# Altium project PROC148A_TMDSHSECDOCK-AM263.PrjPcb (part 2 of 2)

## Sheet PROC148A_HSECMUX.SchDoc
size 431 x 279 mm; Date: Not shown in title block; ApprovedBy: Not shown in title block; CheckedBy: Not shown in title block; Author: Not shown in title block; CompanyName: Not shown in title block; Engineer: Not shown in title block; Organization: Not shown in title block; Address1: Not shown in title block; Address2: Not shown in title block; Address3: Not shown in title block; Address4: Not shown in title block; DocumentNumber: 1; Revision: Use project parameter SCH_Rev; SheetNumber: 5; SheetTotal: 8; PageSetup: Record=PageOptions¦CenterHorizontal=True¦CenterVertical=True¦PrintScale=1.00¦XCorrection=1.00¦YCorrection=1.00¦PrintKind=0¦BorderSize=5000000¦LeftOffset=0¦BottomOffset=0¦Orientation=2¦PaperLength=1000¦PaperWidth=1000¦Scale=100¦PaperSource=15¦PrintQuality=600¦MediaType=1¦DitherType=10¦PaperKind=Letter¦PrintScaleMode=1
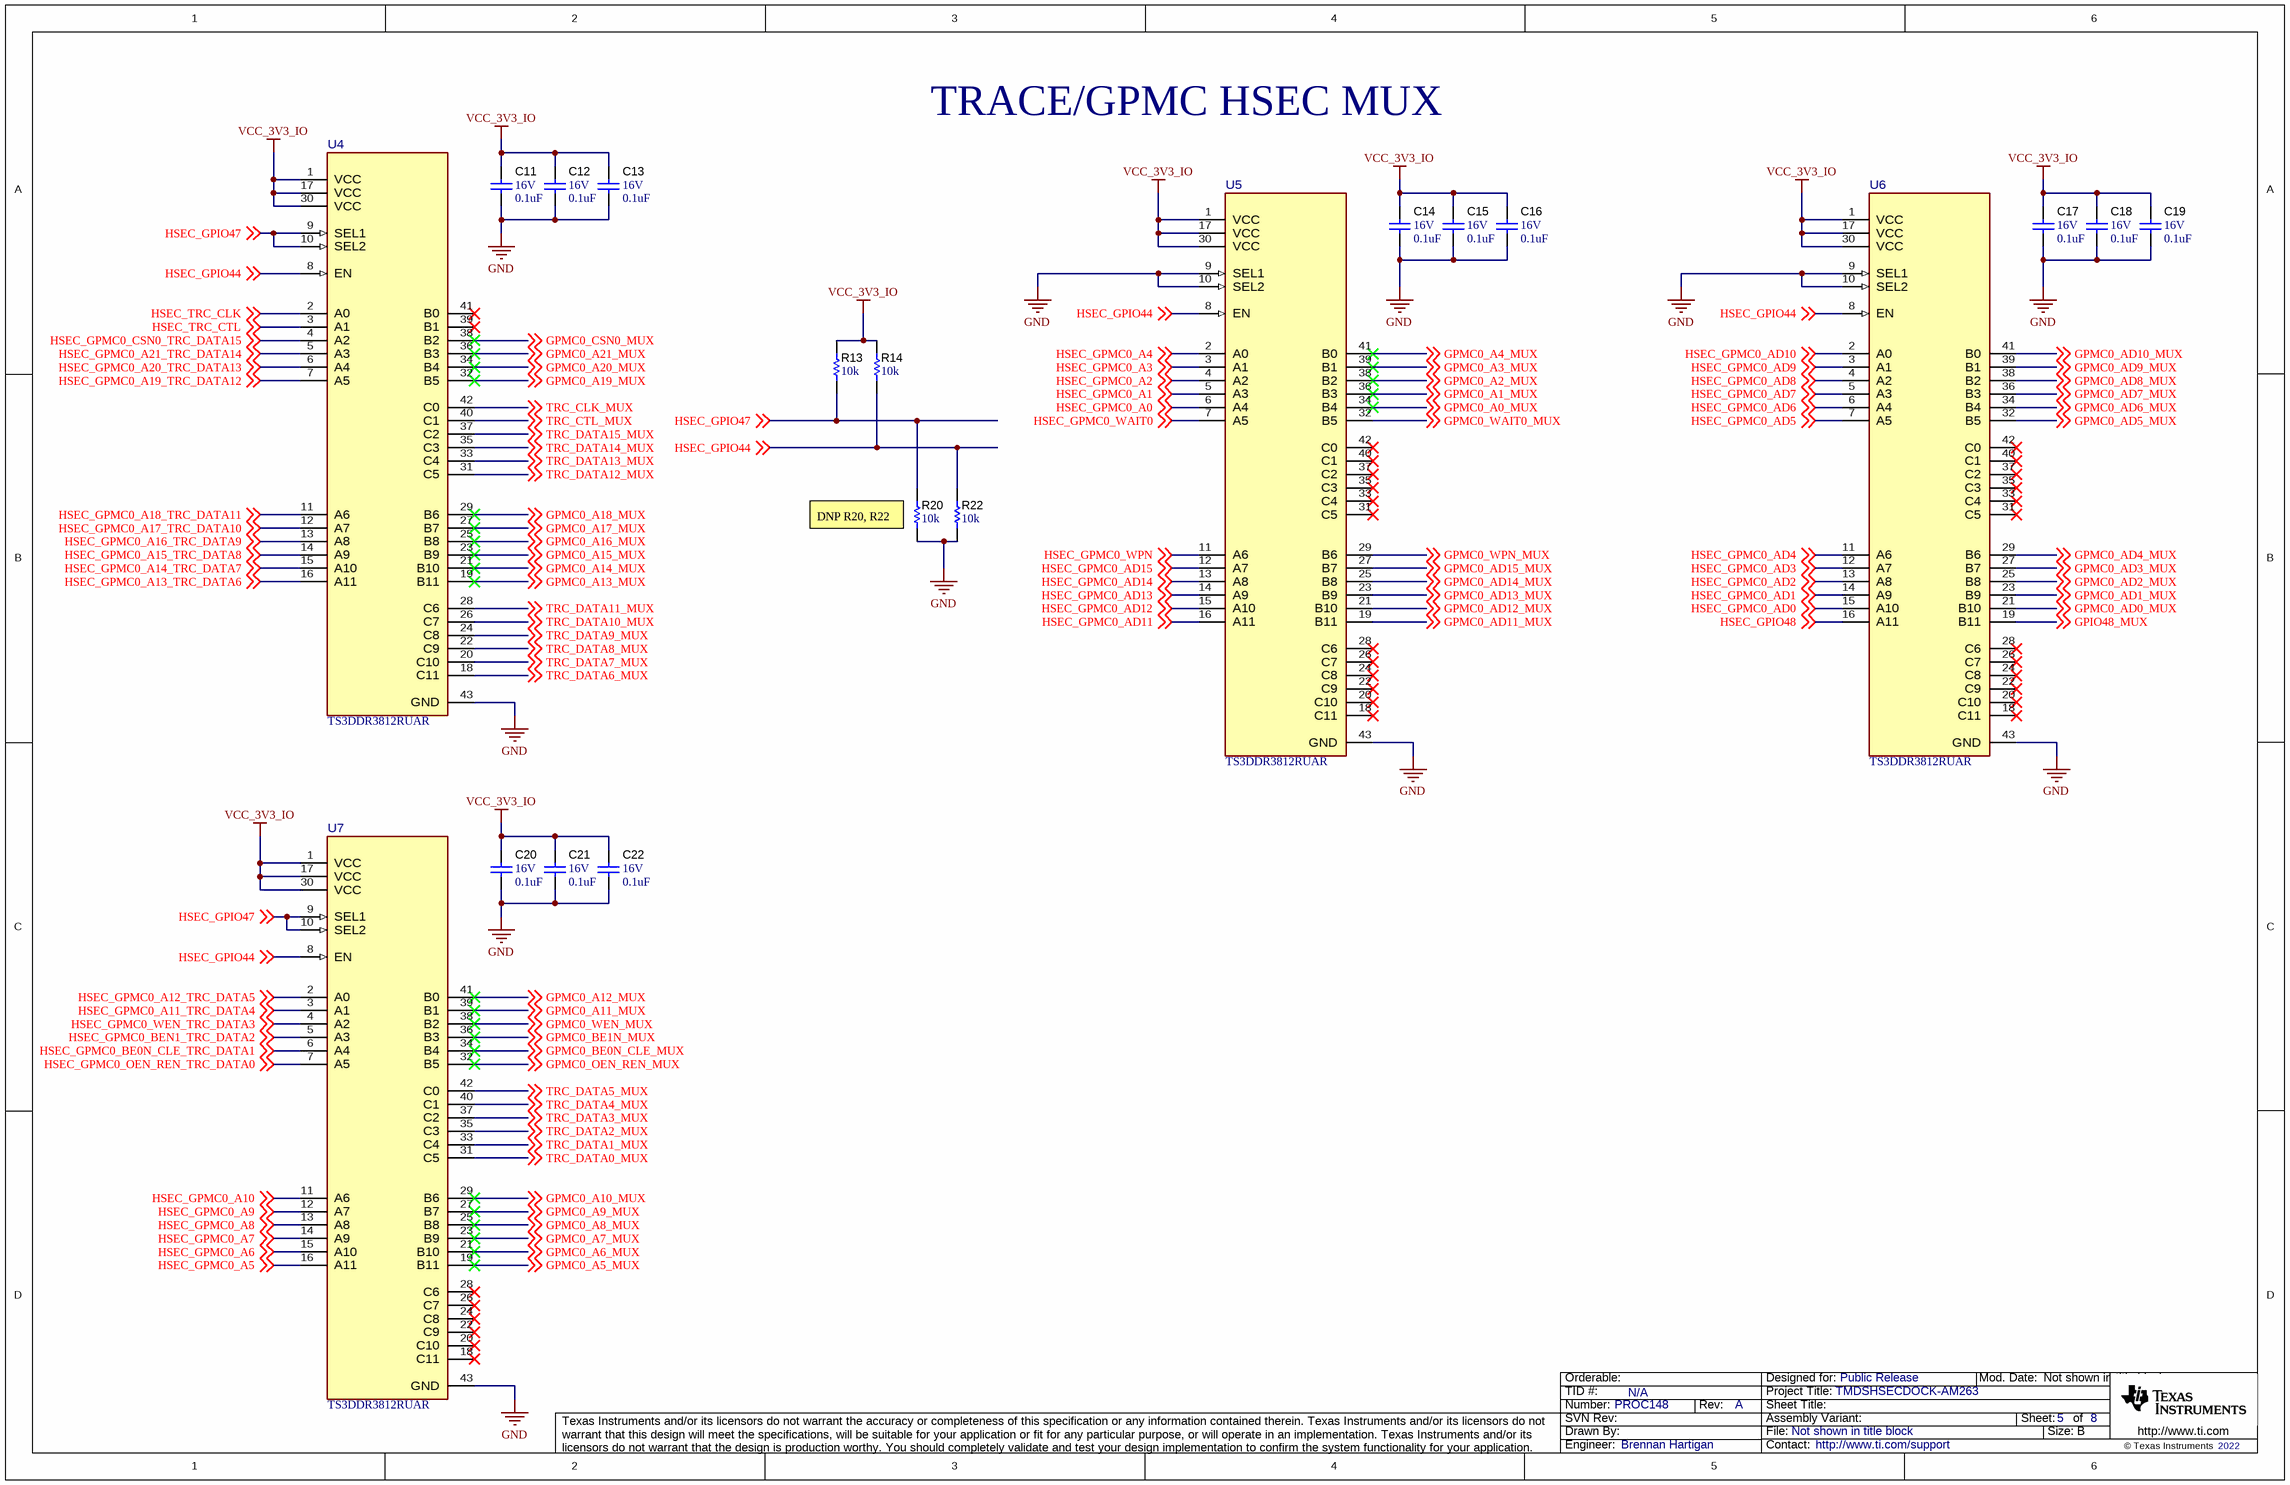
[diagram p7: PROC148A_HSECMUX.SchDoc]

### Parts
C11  VDC_V: 16V  ValueDisplayed: 0.1uF  [0201_033]  (hidden comment: GRM033R61C104KE84D)
C12  VDC_V: 16V  ValueDisplayed: 0.1uF  [0201_033]  (hidden comment: GRM033R61C104KE84D)
C13  VDC_V: 16V  ValueDisplayed: 0.1uF  [0201_033]  (hidden comment: GRM033R61C104KE84D)
C14  VDC_V: 16V  ValueDisplayed: 0.1uF  [0201_033]  (hidden comment: GRM033R61C104KE84D)
C15  VDC_V: 16V  ValueDisplayed: 0.1uF  [0201_033]  (hidden comment: GRM033R61C104KE84D)
C16  VDC_V: 16V  ValueDisplayed: 0.1uF  [0201_033]  (hidden comment: GRM033R61C104KE84D)
C17  VDC_V: 16V  ValueDisplayed: 0.1uF  [0201_033]  (hidden comment: GRM033R61C104KE84D)
C18  VDC_V: 16V  ValueDisplayed: 0.1uF  [0201_033]  (hidden comment: GRM033R61C104KE84D)
C19  VDC_V: 16V  ValueDisplayed: 0.1uF  [0201_033]  (hidden comment: GRM033R61C104KE84D)
C20  VDC_V: 16V  ValueDisplayed: 0.1uF  [0201_033]  (hidden comment: GRM033R61C104KE84D)
C21  VDC_V: 16V  ValueDisplayed: 0.1uF  [0201_033]  (hidden comment: GRM033R61C104KE84D)
C22  VDC_V: 16V  ValueDisplayed: 0.1uF  [0201_033]  (hidden comment: GRM033R61C104KE84D)
R13  ValueDisplayed: 10k  [0402]  (hidden comment: CRCW040210K0JNED)
R14  ValueDisplayed: 10k  [0402]  (hidden comment: CRCW040210K0JNED)
R20  ValueDisplayed: 10k  [0402]  (hidden comment: CRCW040210K0JNED)
R22  ValueDisplayed: 10k  [0402]  (hidden comment: CRCW040210K0JNED)
U4  TS3DDR3812RUAR  [RUA0042A-MFG]
U5  TS3DDR3812RUAR  [RUA0042A-MFG]
U6  TS3DDR3812RUAR  [RUA0042A-MFG]
U7  TS3DDR3812RUAR  [RUA0042A-MFG]

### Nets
GND: C11.2 C12.2 C13.2 C14.2 C15.2 C16.2 C17.2 C18.2 C19.2 C20.2 C21.2 C22.2 R20.1 R22.1 U4.43(GND) U5.9(SEL1) U5.10(SEL2) U5.43(GND) U6.9(SEL1) U6.10(SEL2) U6.43(GND) U7.43(GND)
VCC_3V3_IO: C11.1 C12.1 C13.1 C14.1 C15.1 C16.1 C17.1 C18.1 C19.1 C20.1 C21.1 C22.1 R13.2 R14.2 U4.1(VCC) U4.17(VCC) U4.30(VCC) U5.1(VCC) U5.17(VCC) U5.30(VCC) U6.1(VCC) U6.17(VCC) U6.30(VCC) U7.1(VCC) U7.17(VCC) U7.30(VCC)
GPIO48_MUX: U6.19(B11) ; off-sheet GPIO48_MUX
GPMC0_A0_MUX: U5.34(B4) ; off-sheet GPMC0_A0_MUX
GPMC0_A1_MUX: U5.36(B3) ; off-sheet GPMC0_A1_MUX
GPMC0_A2_MUX: U5.38(B2) ; off-sheet GPMC0_A2_MUX
GPMC0_A3_MUX: U5.39(B1) ; off-sheet GPMC0_A3_MUX
GPMC0_A4_MUX: U5.41(B0) ; off-sheet GPMC0_A4_MUX
GPMC0_A5_MUX: U7.19(B11) ; off-sheet GPMC0_A5_MUX
GPMC0_A6_MUX: U7.21(B10) ; off-sheet GPMC0_A6_MUX
GPMC0_A7_MUX: U7.23(B9) ; off-sheet GPMC0_A7_MUX
GPMC0_A8_MUX: U7.25(B8) ; off-sheet GPMC0_A8_MUX
GPMC0_A9_MUX: U7.27(B7) ; off-sheet GPMC0_A9_MUX
GPMC0_A10_MUX: U7.29(B6) ; off-sheet GPMC0_A10_MUX
GPMC0_A11_MUX: U7.39(B1) ; off-sheet GPMC0_A11_MUX
GPMC0_A12_MUX: U7.41(B0) ; off-sheet GPMC0_A12_MUX
GPMC0_A13_MUX: U4.19(B11) ; off-sheet GPMC0_A13_MUX
GPMC0_A14_MUX: U4.21(B10) ; off-sheet GPMC0_A14_MUX
GPMC0_A15_MUX: U4.23(B9) ; off-sheet GPMC0_A15_MUX
GPMC0_A16_MUX: U4.25(B8) ; off-sheet GPMC0_A16_MUX
GPMC0_A17_MUX: U4.27(B7) ; off-sheet GPMC0_A17_MUX
GPMC0_A18_MUX: U4.29(B6) ; off-sheet GPMC0_A18_MUX
GPMC0_A19_MUX: U4.32(B5) ; off-sheet GPMC0_A19_MUX
GPMC0_A20_MUX: U4.34(B4) ; off-sheet GPMC0_A20_MUX
GPMC0_A21_MUX: U4.36(B3) ; off-sheet GPMC0_A21_MUX
GPMC0_AD0_MUX: U6.21(B10) ; off-sheet GPMC0_AD0_MUX
GPMC0_AD1_MUX: U6.23(B9) ; off-sheet GPMC0_AD1_MUX
GPMC0_AD2_MUX: U6.25(B8) ; off-sheet GPMC0_AD2_MUX
GPMC0_AD3_MUX: U6.27(B7) ; off-sheet GPMC0_AD3_MUX
GPMC0_AD4_MUX: U6.29(B6) ; off-sheet GPMC0_AD4_MUX
GPMC0_AD5_MUX: U6.32(B5) ; off-sheet GPMC0_AD5_MUX
GPMC0_AD6_MUX: U6.34(B4) ; off-sheet GPMC0_AD6_MUX
GPMC0_AD7_MUX: U6.36(B3) ; off-sheet GPMC0_AD7_MUX
GPMC0_AD8_MUX: U6.38(B2) ; off-sheet GPMC0_AD8_MUX
GPMC0_AD9_MUX: U6.39(B1) ; off-sheet GPMC0_AD9_MUX
GPMC0_AD10_MUX: U6.41(B0) ; off-sheet GPMC0_AD10_MUX
GPMC0_AD11_MUX: U5.19(B11) ; off-sheet GPMC0_AD11_MUX
GPMC0_AD12_MUX: U5.21(B10) ; off-sheet GPMC0_AD12_MUX
GPMC0_AD13_MUX: U5.23(B9) ; off-sheet GPMC0_AD13_MUX
GPMC0_AD14_MUX: U5.25(B8) ; off-sheet GPMC0_AD14_MUX
GPMC0_AD15_MUX: U5.27(B7) ; off-sheet GPMC0_AD15_MUX
GPMC0_BE0N_CLE_MUX: U7.34(B4) ; off-sheet GPMC0_BE0N_CLE_MUX
GPMC0_BE1N_MUX: U7.36(B3) ; off-sheet GPMC0_BE1N_MUX
GPMC0_CSN0_MUX: U4.38(B2) ; off-sheet GPMC0_CSN0_MUX
GPMC0_OEN_REN_MUX: U7.32(B5) ; off-sheet GPMC0_OEN_REN_MUX
GPMC0_WAIT0_MUX: U5.32(B5) ; off-sheet GPMC0_WAIT0_MUX
GPMC0_WEN_MUX: U7.38(B2) ; off-sheet GPMC0_WEN_MUX
GPMC0_WPN_MUX: U5.29(B6) ; off-sheet GPMC0_WPN_MUX
HSEC_GPIO44: R14.1 R22.2 U4.8(EN) U5.8(EN) U6.8(EN) U7.8(EN) ; off-sheet HSEC_GPIO44
HSEC_GPIO47: R13.1 R20.2 U4.9(SEL1) U4.10(SEL2) U7.9(SEL1) U7.10(SEL2) ; off-sheet HSEC_GPIO47
HSEC_GPIO48: U6.16(A11) ; off-sheet HSEC_GPIO48
HSEC_GPMC0_A0: U5.6(A4) ; off-sheet HSEC_GPMC0_A0
HSEC_GPMC0_A1: U5.5(A3) ; off-sheet HSEC_GPMC0_A1
HSEC_GPMC0_A2: U5.4(A2) ; off-sheet HSEC_GPMC0_A2
HSEC_GPMC0_A3: U5.3(A1) ; off-sheet HSEC_GPMC0_A3
HSEC_GPMC0_A4: U5.2(A0) ; off-sheet HSEC_GPMC0_A4
HSEC_GPMC0_A5: U7.16(A11) ; off-sheet HSEC_GPMC0_A5
HSEC_GPMC0_A6: U7.15(A10) ; off-sheet HSEC_GPMC0_A6
HSEC_GPMC0_A7: U7.14(A9) ; off-sheet HSEC_GPMC0_A7
HSEC_GPMC0_A8: U7.13(A8) ; off-sheet HSEC_GPMC0_A8
HSEC_GPMC0_A9: U7.12(A7) ; off-sheet HSEC_GPMC0_A9
HSEC_GPMC0_A10: U7.11(A6) ; off-sheet HSEC_GPMC0_A10
HSEC_GPMC0_A11_TRC_DATA4: U7.3(A1) ; off-sheet HSEC_GPMC0_A11_TRC_DATA4
HSEC_GPMC0_A12_TRC_DATA5: U7.2(A0) ; off-sheet HSEC_GPMC0_A12_TRC_DATA5
HSEC_GPMC0_A13_TRC_DATA6: U4.16(A11) ; off-sheet HSEC_GPMC0_A13_TRC_DATA6
HSEC_GPMC0_A14_TRC_DATA7: U4.15(A10) ; off-sheet HSEC_GPMC0_A14_TRC_DATA7
HSEC_GPMC0_A15_TRC_DATA8: U4.14(A9) ; off-sheet HSEC_GPMC0_A15_TRC_DATA8
HSEC_GPMC0_A16_TRC_DATA9: U4.13(A8) ; off-sheet HSEC_GPMC0_A16_TRC_DATA9
HSEC_GPMC0_A17_TRC_DATA10: U4.12(A7) ; off-sheet HSEC_GPMC0_A17_TRC_DATA10
HSEC_GPMC0_A18_TRC_DATA11: U4.11(A6) ; off-sheet HSEC_GPMC0_A18_TRC_DATA11
HSEC_GPMC0_A19_TRC_DATA12: U4.7(A5) ; off-sheet HSEC_GPMC0_A19_TRC_DATA12
HSEC_GPMC0_A20_TRC_DATA13: U4.6(A4) ; off-sheet HSEC_GPMC0_A20_TRC_DATA13
HSEC_GPMC0_A21_TRC_DATA14: U4.5(A3) ; off-sheet HSEC_GPMC0_A21_TRC_DATA14
HSEC_GPMC0_AD0: U6.15(A10) ; off-sheet HSEC_GPMC0_AD0
HSEC_GPMC0_AD1: U6.14(A9) ; off-sheet HSEC_GPMC0_AD1
HSEC_GPMC0_AD2: U6.13(A8) ; off-sheet HSEC_GPMC0_AD2
HSEC_GPMC0_AD3: U6.12(A7) ; off-sheet HSEC_GPMC0_AD3
HSEC_GPMC0_AD4: U6.11(A6) ; off-sheet HSEC_GPMC0_AD4
HSEC_GPMC0_AD5: U6.7(A5) ; off-sheet HSEC_GPMC0_AD5
HSEC_GPMC0_AD6: U6.6(A4) ; off-sheet HSEC_GPMC0_AD6
HSEC_GPMC0_AD7: U6.5(A3) ; off-sheet HSEC_GPMC0_AD7
HSEC_GPMC0_AD8: U6.4(A2) ; off-sheet HSEC_GPMC0_AD8
HSEC_GPMC0_AD9: U6.3(A1) ; off-sheet HSEC_GPMC0_AD9
HSEC_GPMC0_AD10: U6.2(A0) ; off-sheet HSEC_GPMC0_AD10
HSEC_GPMC0_AD11: U5.16(A11) ; off-sheet HSEC_GPMC0_AD11
HSEC_GPMC0_AD12: U5.15(A10) ; off-sheet HSEC_GPMC0_AD12
HSEC_GPMC0_AD13: U5.14(A9) ; off-sheet HSEC_GPMC0_AD13
HSEC_GPMC0_AD14: U5.13(A8) ; off-sheet HSEC_GPMC0_AD14
HSEC_GPMC0_AD15: U5.12(A7) ; off-sheet HSEC_GPMC0_AD15
HSEC_GPMC0_BE0N_CLE_TRC_DATA1: U7.6(A4) ; off-sheet HSEC_GPMC0_BE0N_CLE_TRC_DATA1
HSEC_GPMC0_BEN1_TRC_DATA2: U7.5(A3) ; off-sheet HSEC_GPMC0_BEN1_TRC_DATA2
HSEC_GPMC0_CSN0_TRC_DATA15: U4.4(A2) ; off-sheet HSEC_GPMC0_CSN0_TRC_DATA15
HSEC_GPMC0_OEN_REN_TRC_DATA0: U7.7(A5) ; off-sheet HSEC_GPMC0_OEN_REN_TRC_DATA0
HSEC_GPMC0_WAIT0: U5.7(A5) ; off-sheet HSEC_GPMC0_WAIT0
HSEC_GPMC0_WEN_TRC_DATA3: U7.4(A2) ; off-sheet HSEC_GPMC0_WEN_TRC_DATA3
HSEC_GPMC0_WPN: U5.11(A6) ; off-sheet HSEC_GPMC0_WPN
HSEC_TRC_CLK: U4.2(A0) ; off-sheet HSEC_TRC_CLK
HSEC_TRC_CTL: U4.3(A1) ; off-sheet HSEC_TRC_CTL
TRC_CLK_MUX: U4.42(C0) ; off-sheet TRC_CLK_MUX
TRC_CTL_MUX: U4.40(C1) ; off-sheet TRC_CTL_MUX
TRC_DATA0_MUX: U7.31(C5) ; off-sheet TRC_DATA0_MUX
TRC_DATA1_MUX: U7.33(C4) ; off-sheet TRC_DATA1_MUX
TRC_DATA2_MUX: U7.35(C3) ; off-sheet TRC_DATA2_MUX
TRC_DATA3_MUX: U7.37(C2) ; off-sheet TRC_DATA3_MUX
TRC_DATA4_MUX: U7.40(C1) ; off-sheet TRC_DATA4_MUX
TRC_DATA5_MUX: U7.42(C0) ; off-sheet TRC_DATA5_MUX
TRC_DATA6_MUX: U4.18(C11) ; off-sheet TRC_DATA6_MUX
TRC_DATA7_MUX: U4.20(C10) ; off-sheet TRC_DATA7_MUX
TRC_DATA8_MUX: U4.22(C9) ; off-sheet TRC_DATA8_MUX
TRC_DATA9_MUX: U4.24(C8) ; off-sheet TRC_DATA9_MUX
TRC_DATA10_MUX: U4.26(C7) ; off-sheet TRC_DATA10_MUX
TRC_DATA11_MUX: U4.28(C6) ; off-sheet TRC_DATA11_MUX
TRC_DATA12_MUX: U4.31(C5) ; off-sheet TRC_DATA12_MUX
TRC_DATA13_MUX: U4.33(C4) ; off-sheet TRC_DATA13_MUX
TRC_DATA14_MUX: U4.35(C3) ; off-sheet TRC_DATA14_MUX
TRC_DATA15_MUX: U4.37(C2) ; off-sheet TRC_DATA15_MUX

Not connected (* = marked no-connect by the designer): U4 39(B1)* 41(B0)*; U5 18(C11)* 20(C10)* 22(C9)* 24(C8)* 26(C7)* 28(C6)* 31(C5)* 33(C4)* 35(C3)* 37(C2)* 40(C1)* 42(C0)*; U6 18(C11)* 20(C10)* 22(C9)* 24(C8)* 26(C7)* 28(C6)* 31(C5)* 33(C4)* 35(C3)* 37(C2)* 40(C1)* 42(C0)*; U7 18(C11)* 20(C10)* 22(C9)* 24(C8)* 26(C7)* 28(C6)*

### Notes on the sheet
- TRACE/GPMC HSEC MUX
- (near R20) DNP R20, R22

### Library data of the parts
C11-C22 = CMP-0009717-2: CAP, CERM, 0.1 uF, 16 V, +/- 10%, X5R, 0201; Manufacturer: MuRata; TaMin_C: -55°C; Polarized: N; SizeAreaWB_mm2: 2.08; Value1: Unknown; U/M: EA; Value: 0.1uF; TaMax_C: 85°C; SizeZ_mm: 0.33; SizeX_mm: 0.6; SizeY_mm: 0.3; Cap_Case: 0201; SizeArea_mm2: 0.18; Cap_F: 100nF; AEC Category: Q200
R13 R14 R20 R22 = CMP-0026825-5: RES, 10 k, 5%, 0.063 W, AEC-Q200 Grade 0, 0402; Manufacturer: Vishay-Dale; Power_W: 63mW; TempCo: 200 ppm/C; Value_Code: 10k0; Value: 10k; EIA_Code: E24; SizeX_mm: 1; SizeY_mm: 0.5; SizeZ_mm: 0.6; Value2: 0.063W; AEC Qualified: Y; VDC_V: 50V; AEC Category: Q200; AEC Grade: 0
U4-U7 = CMP-0093539-2: IC MUX/DEMUX DDR3 1:2 42WQFN; Manufacturer: Texas Instruments; TaMax_C: +85°C; AEC Qualified: No; Nominal Supply Current: 300uA; On State Resistance: 8Ω; Standoff Height: 0mm; Min Supply Voltage: 3V; Max Supply Voltage: 3.6V; AEC Category: Q200; SizeZ_mm: 0.8mm; TaMin_C: -40°C; PositionCount: 12; -3Db Bandwith: 1.675GHz

## Sheet PROC148A_PSRAM.SchDoc
size 431 x 279 mm; Date: Not shown in title block; ApprovedBy: Not shown in title block; CheckedBy: Not shown in title block; Author: Not shown in title block; CompanyName: Not shown in title block; Engineer: Not shown in title block; Organization: Not shown in title block; Address1: Not shown in title block; Address2: Not shown in title block; Address3: Not shown in title block; Address4: Not shown in title block; DocumentNumber: 1; Revision: Use project parameter SCH_Rev; SheetNumber: 6; SheetTotal: 8; PageSetup: Record=PageOptions¦CenterHorizontal=True¦CenterVertical=True¦PrintScale=1.00¦XCorrection=1.00¦YCorrection=1.00¦PrintKind=0¦BorderSize=5000000¦LeftOffset=0¦BottomOffset=0¦Orientation=2¦PaperLength=1000¦PaperWidth=1000¦Scale=100¦PaperSource=15¦PrintQuality=600¦MediaType=1¦DitherType=10¦PaperKind=Letter¦PrintScaleMode=1
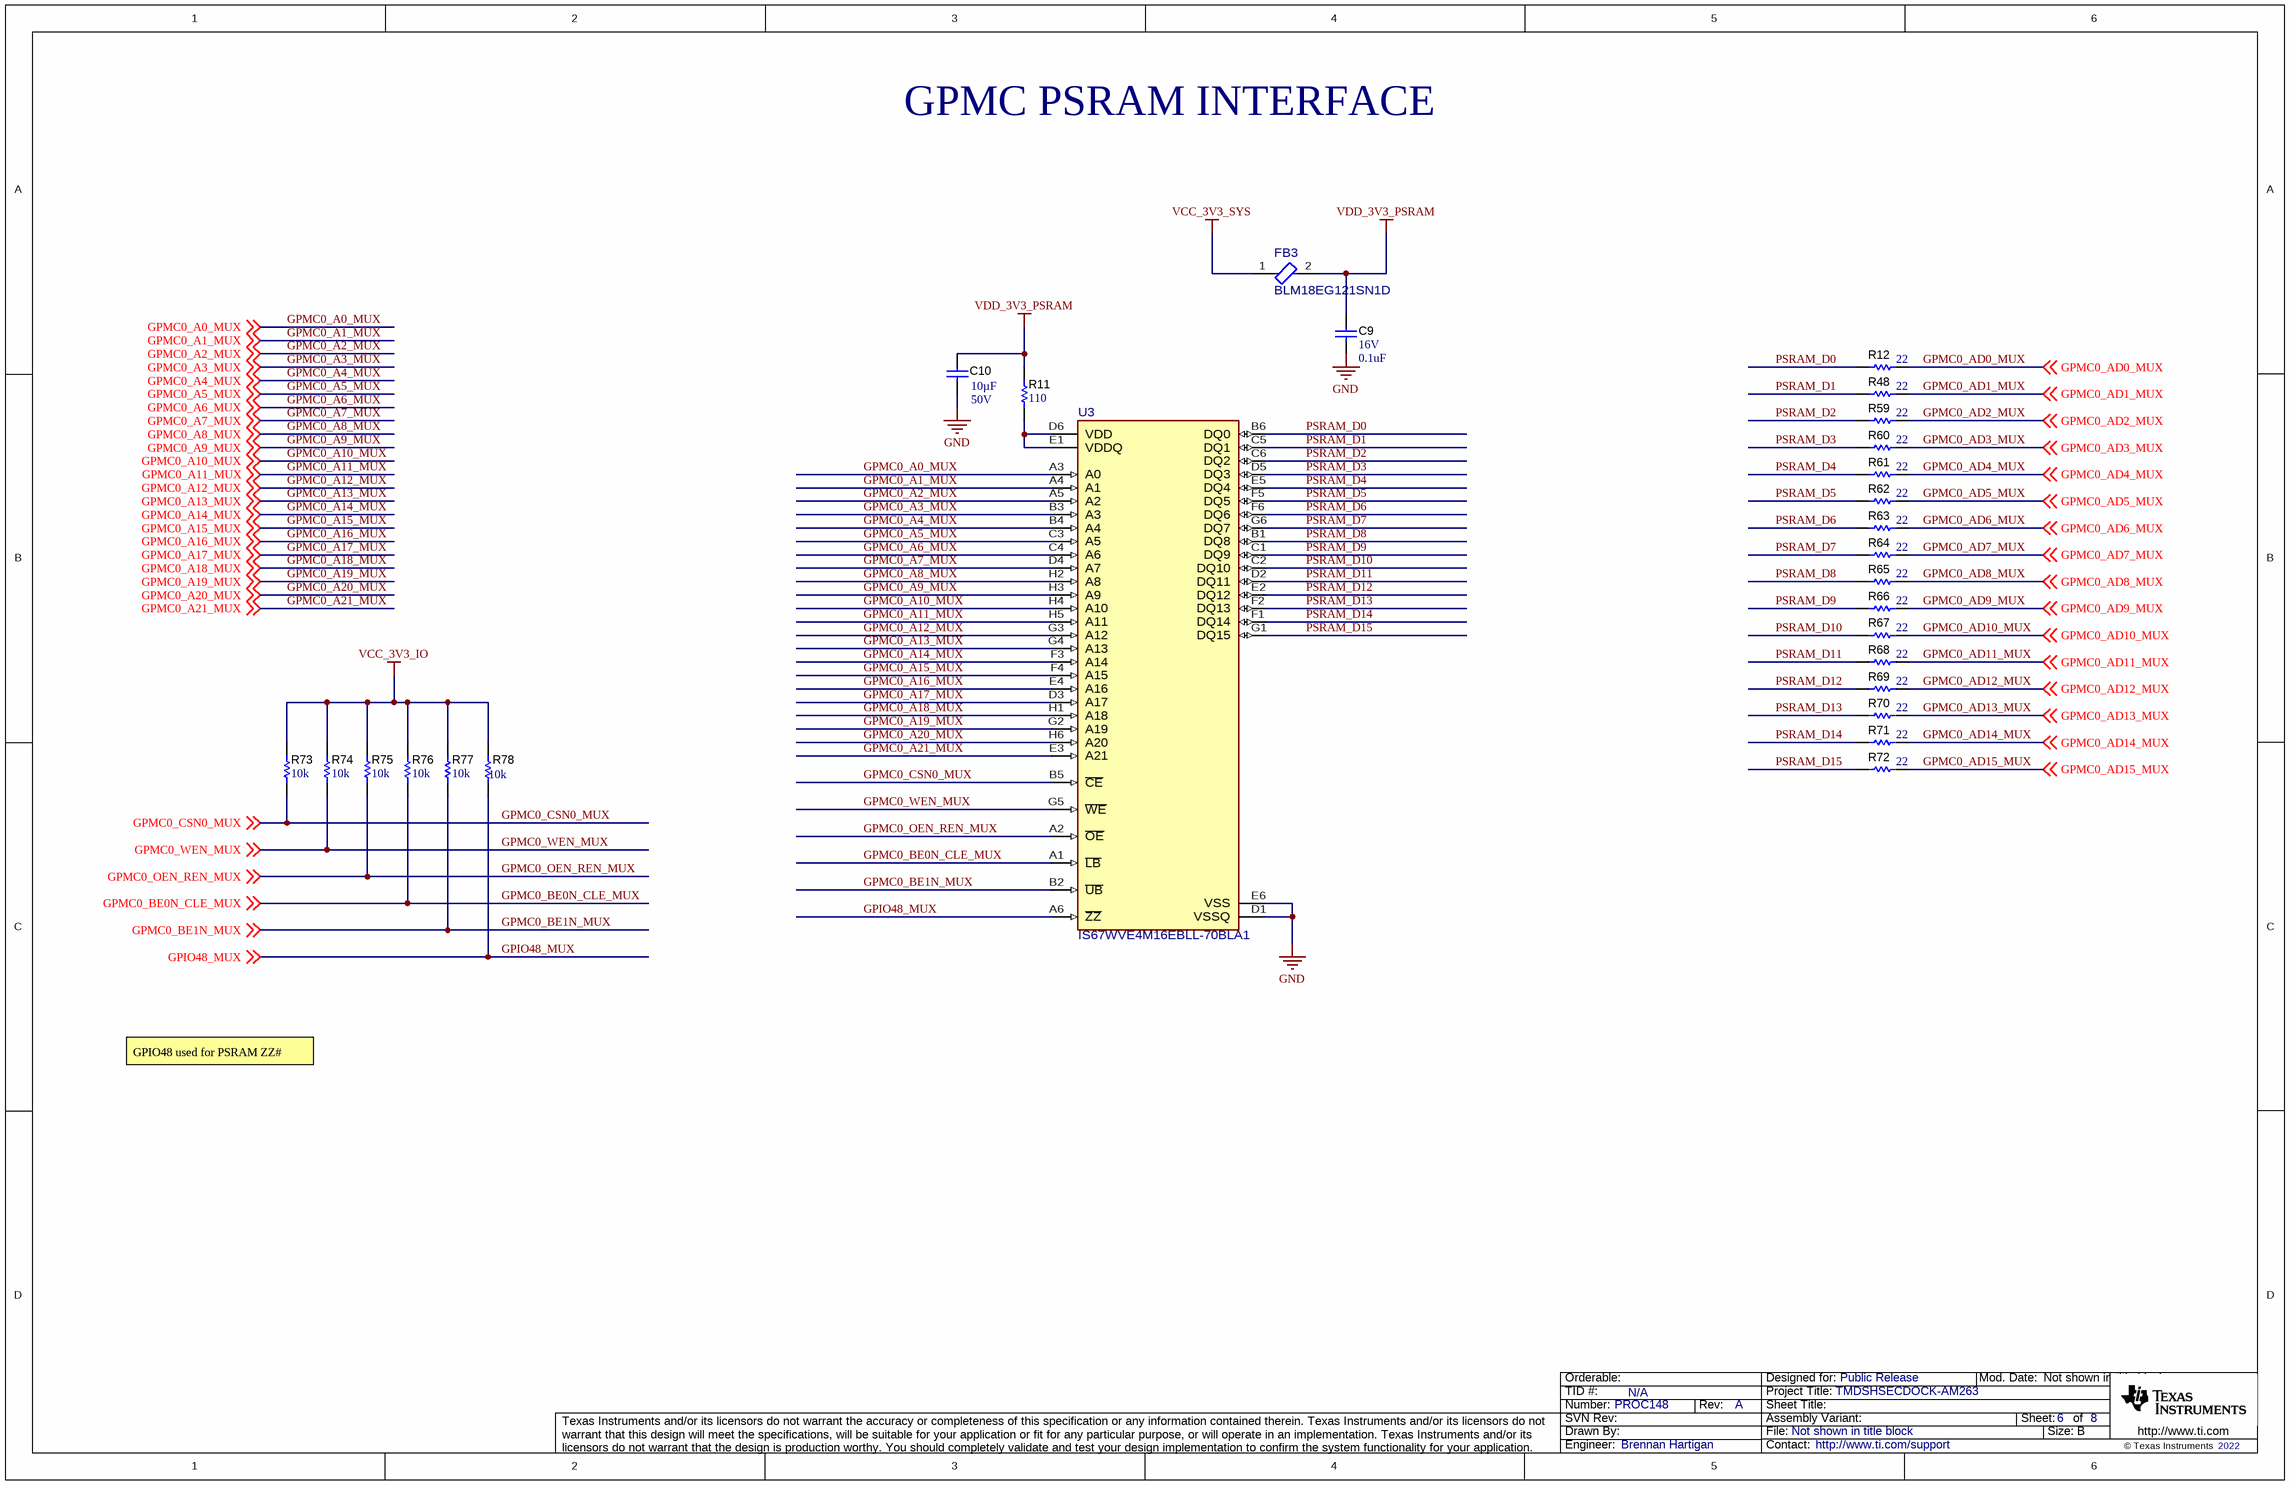
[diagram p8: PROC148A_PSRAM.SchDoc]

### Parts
C9  VDC_V: 16V  ValueDisplayed: 0.1uF  [0201_033]  (hidden comment: GRM033R61C104KE84D)
C10  VDC_V: 50V  ValueDisplayed: 10µF  [1210_270]  (hidden comment: CL32B106KBJNNWE)
FB3  BLM18EG121SN1D  [FP-BLM18EG121SN1D_0603-MFG]
R11  ValueDisplayed: 110  [0402]  (hidden comment: CRCW0402110RJNED)
R12  ValueDisplayed: 22  [0402]  (hidden comment: CRCW040222R0JNED)
R48  ValueDisplayed: 22  [0402]  (hidden comment: CRCW040222R0JNED)
R59  ValueDisplayed: 22  [0402]  (hidden comment: CRCW040222R0JNED)
R60  ValueDisplayed: 22  [0402]  (hidden comment: CRCW040222R0JNED)
R61  ValueDisplayed: 22  [0402]  (hidden comment: CRCW040222R0JNED)
R62  ValueDisplayed: 22  [0402]  (hidden comment: CRCW040222R0JNED)
R63  ValueDisplayed: 22  [0402]  (hidden comment: CRCW040222R0JNED)
R64  ValueDisplayed: 22  [0402]  (hidden comment: CRCW040222R0JNED)
R65  ValueDisplayed: 22  [0402]  (hidden comment: CRCW040222R0JNED)
R66  ValueDisplayed: 22  [0402]  (hidden comment: CRCW040222R0JNED)
R67  ValueDisplayed: 22  [0402]  (hidden comment: CRCW040222R0JNED)
R68  ValueDisplayed: 22  [0402]  (hidden comment: CRCW040222R0JNED)
R69  ValueDisplayed: 22  [0402]  (hidden comment: CRCW040222R0JNED)
R70  ValueDisplayed: 22  [0402]  (hidden comment: CRCW040222R0JNED)
R71  ValueDisplayed: 22  [0402]  (hidden comment: CRCW040222R0JNED)
R72  ValueDisplayed: 22  [0402]  (hidden comment: CRCW040222R0JNED)
R73  ValueDisplayed: 10k  [0402]  (hidden comment: CRCW040210K0JNED)
R74  ValueDisplayed: 10k  [0402]  (hidden comment: CRCW040210K0JNED)
R75  ValueDisplayed: 10k  [0402]  (hidden comment: CRCW040210K0JNED)
R76  ValueDisplayed: 10k  [0402]  (hidden comment: CRCW040210K0JNED)
R77  ValueDisplayed: 10k  [0402]  (hidden comment: CRCW040210K0JNED)
R78  ValueDisplayed: 10k  [0402]  (hidden comment: CRCW040210K0JNED)
U3  IS67WVE4M16EBLL-70BLA1  [FP-IS67WVE4M16EBLL-70BLA1_TFBGA48-IPC_C]

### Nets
GND: C9.2 C10.2 U3.D1(VSSQ) U3.E6(VSS)
VCC_3V3_IO: R73.2 R74.2 R75.2 R76.2 R77.2 R78.2
VCC_3V3_SYS: FB3.1
VDD_3V3_PSRAM: C9.1 C10.1 FB3.2 R11.2
GPIO48_MUX: R78.1 U3.A6(~{ZZ}) ; off-sheet GPIO48_MUX
GPMC0_A0_MUX: U3.A3(A0) ; off-sheet GPMC0_A0_MUX
GPMC0_A1_MUX: U3.A4(A1) ; off-sheet GPMC0_A1_MUX
GPMC0_A2_MUX: U3.A5(A2) ; off-sheet GPMC0_A2_MUX
GPMC0_A3_MUX: U3.B3(A3) ; off-sheet GPMC0_A3_MUX
GPMC0_A4_MUX: U3.B4(A4) ; off-sheet GPMC0_A4_MUX
GPMC0_A5_MUX: U3.C3(A5) ; off-sheet GPMC0_A5_MUX
GPMC0_A6_MUX: U3.C4(A6) ; off-sheet GPMC0_A6_MUX
GPMC0_A7_MUX: U3.D4(A7) ; off-sheet GPMC0_A7_MUX
GPMC0_A8_MUX: U3.H2(A8) ; off-sheet GPMC0_A8_MUX
GPMC0_A9_MUX: U3.H3(A9) ; off-sheet GPMC0_A9_MUX
GPMC0_A10_MUX: U3.H4(A10) ; off-sheet GPMC0_A10_MUX
GPMC0_A11_MUX: U3.H5(A11) ; off-sheet GPMC0_A11_MUX
GPMC0_A12_MUX: U3.G3(A12) ; off-sheet GPMC0_A12_MUX
GPMC0_A13_MUX: U3.G4(A13) ; off-sheet GPMC0_A13_MUX
GPMC0_A14_MUX: U3.F3(A14) ; off-sheet GPMC0_A14_MUX
GPMC0_A15_MUX: U3.F4(A15) ; off-sheet GPMC0_A15_MUX
GPMC0_A16_MUX: U3.E4(A16) ; off-sheet GPMC0_A16_MUX
GPMC0_A17_MUX: U3.D3(A17) ; off-sheet GPMC0_A17_MUX
GPMC0_A18_MUX: U3.H1(A18) ; off-sheet GPMC0_A18_MUX
GPMC0_A19_MUX: U3.G2(A19) ; off-sheet GPMC0_A19_MUX
GPMC0_A20_MUX: U3.H6(A20) ; off-sheet GPMC0_A20_MUX
GPMC0_A21_MUX: U3.E3(A21) ; off-sheet GPMC0_A21_MUX
GPMC0_AD0_MUX: R12.2 ; off-sheet GPMC0_AD0_MUX
GPMC0_AD1_MUX: R48.2 ; off-sheet GPMC0_AD1_MUX
GPMC0_AD2_MUX: R59.2 ; off-sheet GPMC0_AD2_MUX
GPMC0_AD3_MUX: R60.2 ; off-sheet GPMC0_AD3_MUX
GPMC0_AD4_MUX: R61.2 ; off-sheet GPMC0_AD4_MUX
GPMC0_AD5_MUX: R62.2 ; off-sheet GPMC0_AD5_MUX
GPMC0_AD6_MUX: R63.2 ; off-sheet GPMC0_AD6_MUX
GPMC0_AD7_MUX: R64.2 ; off-sheet GPMC0_AD7_MUX
GPMC0_AD8_MUX: R65.2 ; off-sheet GPMC0_AD8_MUX
GPMC0_AD9_MUX: R66.2 ; off-sheet GPMC0_AD9_MUX
GPMC0_AD10_MUX: R67.2 ; off-sheet GPMC0_AD10_MUX
GPMC0_AD11_MUX: R68.2 ; off-sheet GPMC0_AD11_MUX
GPMC0_AD12_MUX: R69.2 ; off-sheet GPMC0_AD12_MUX
GPMC0_AD13_MUX: R70.2 ; off-sheet GPMC0_AD13_MUX
GPMC0_AD14_MUX: R71.2 ; off-sheet GPMC0_AD14_MUX
GPMC0_AD15_MUX: R72.2 ; off-sheet GPMC0_AD15_MUX
GPMC0_BE0N_CLE_MUX: R76.1 U3.A1(~{LB}) ; off-sheet GPMC0_BE0N_CLE_MUX
GPMC0_BE1N_MUX: R77.1 U3.B2(~{UB}) ; off-sheet GPMC0_BE1N_MUX
GPMC0_CSN0_MUX: R73.1 U3.B5(~{CE}) ; off-sheet GPMC0_CSN0_MUX
GPMC0_OEN_REN_MUX: R75.1 U3.A2(~{OE}) ; off-sheet GPMC0_OEN_REN_MUX
GPMC0_WEN_MUX: R74.1 U3.G5(~{WE}) ; off-sheet GPMC0_WEN_MUX
PSRAM_D0: R12.1 U3.B6(DQ0)
PSRAM_D1: R48.1 U3.C5(DQ1)
PSRAM_D2: R59.1 U3.C6(DQ2)
PSRAM_D3: R60.1 U3.D5(DQ3)
PSRAM_D4: R61.1 U3.E5(DQ4)
PSRAM_D5: R62.1 U3.F5(DQ5)
PSRAM_D6: R63.1 U3.F6(DQ6)
PSRAM_D7: R64.1 U3.G6(DQ7)
PSRAM_D8: R65.1 U3.B1(DQ8)
PSRAM_D9: R66.1 U3.C1(DQ9)
PSRAM_D10: R67.1 U3.C2(DQ10)
PSRAM_D11: R68.1 U3.D2(DQ11)
PSRAM_D12: R69.1 U3.E2(DQ12)
PSRAM_D13: R70.1 U3.F2(DQ13)
PSRAM_D14: R71.1 U3.F1(DQ14)
PSRAM_D15: R72.1 U3.G1(DQ15)
NetR11_1: R11.1 U3.D6(VDD) U3.E1(VDDQ)

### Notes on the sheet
- GPMC PSRAM INTERFACE
- GPIO48 used for PSRAM ZZ#
- Labels drawn without touching a wire or pin: ~{}

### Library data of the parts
C9 = CMP-0009717-2: as C11-C22 on sheet PROC148A_HSECMUX
C10 = CMP-0079201-1: CAP, CERM, 10 µF, 50 V,+/- 10%, X7R, 1210; Manufacturer: Samsung Electro-Mechanics; TaMin_C: -55°C; ESR_ohm: 5m; Polarized: N; SizeAreaWB_mm2: 14.7; Value1: 0.005 ohm; U/M: EA; Value: 10uF; TaMax_C: 125°C; SizeZ_mm: 2.7; SizeX_mm: 3.2; SizeY_mm: 2.5; Cap_Case: 1210; SizeArea_mm2: 8; AEC Category: Q200
FB3 = CMP-0089199-1: 120 Ohms @ 100MHz 1  Ferrite Bead 0603 (1608 Metric) 2A 40mOhm; Manufacturer: Murata; DCR_ohm: 60m; AEC Qualified: No; Tolerance_%: 25%; SizeZ_mm: 0.95mm; Impedance At Frequency: 120Ω @ 100MHz
R11 = CMP-0026829-3: RES, 110, 5%, 0.063 W, AEC-Q200 Grade 0, 0402; Manufacturer: Vishay-Dale; Power_W: 63mW; TempCo: 200 ppm/C; Value_Code: 110R; Value: 110; EIA_Code: E24; SizeX_mm: 1; SizeY_mm: 0.5; SizeZ_mm: 0.6; Value2: 0.063W; AEC Qualified: Y; VDC_V: 50V; AEC Category: Q200; AEC Grade: 0
R12 R48 R59-R72 = CMP-0026880-3: RES, 22, 5%, 0.063 W, AEC-Q200 Grade 0, 0402; Manufacturer: Vishay-Dale; Power_W: 63mW; TempCo: 200 ppm/C; Value_Code: 22R0; Value: 22; EIA_Code: E24; SizeX_mm: 1; SizeY_mm: 0.5; SizeZ_mm: 0.6; Value2: 0.063W; AEC Qualified: Y; VDC_V: 50V; AEC Category: Q200; AEC Grade: 0
R73-R78 = CMP-0026825-5: as R13 on sheet PROC148A_HSECMUX
U3 = CMP-0095867-1: Cellular RAM Pseudo SRAM, 4Mx16, 1.7 to 1.95V, 70ns, TFBGA-48; Manufacturer: ISSI; Memory Size: 4Mbits; Nominal Supply Current: 20-25mA; Interface: Parallel; AEC Qualified: Yes; Max Supply Voltage: 3.6V; Min Supply Voltage: 1.7V; Standoff Height: 0.2mm; AEC Grade: Grade 3; SizeZ_mm: 1.2mm

## Sheet PROC148A_GPMC_interface.SchDoc
size B; Date: Not shown in title block; ApprovedBy: Not shown in title block; CheckedBy: Not shown in title block; Author: Not shown in title block; CompanyName: Not shown in title block; Engineer: Not shown in title block; Organization: Not shown in title block; Address1: Not shown in title block; Address2: Not shown in title block; Address3: Not shown in title block; Address4: Not shown in title block; DocumentNumber: 2; Revision: Use project parameter SCH_Rev; SheetNumber: 7; SheetTotal: 9; PageSetup: Record=PageOptions¦CenterHorizontal=True¦CenterVertical=True¦PrintScale=1.00¦XCorrection=1.00¦YCorrection=1.00¦PrintKind=0¦BorderSize=5000000¦LeftOffset=0¦BottomOffset=0¦Orientation=2¦PaperLength=1000¦PaperWidth=1000¦Scale=100¦PaperSource=15¦PrintQuality=600¦MediaType=1¦DitherType=10¦PaperKind=Letter¦PrintScaleMode=1
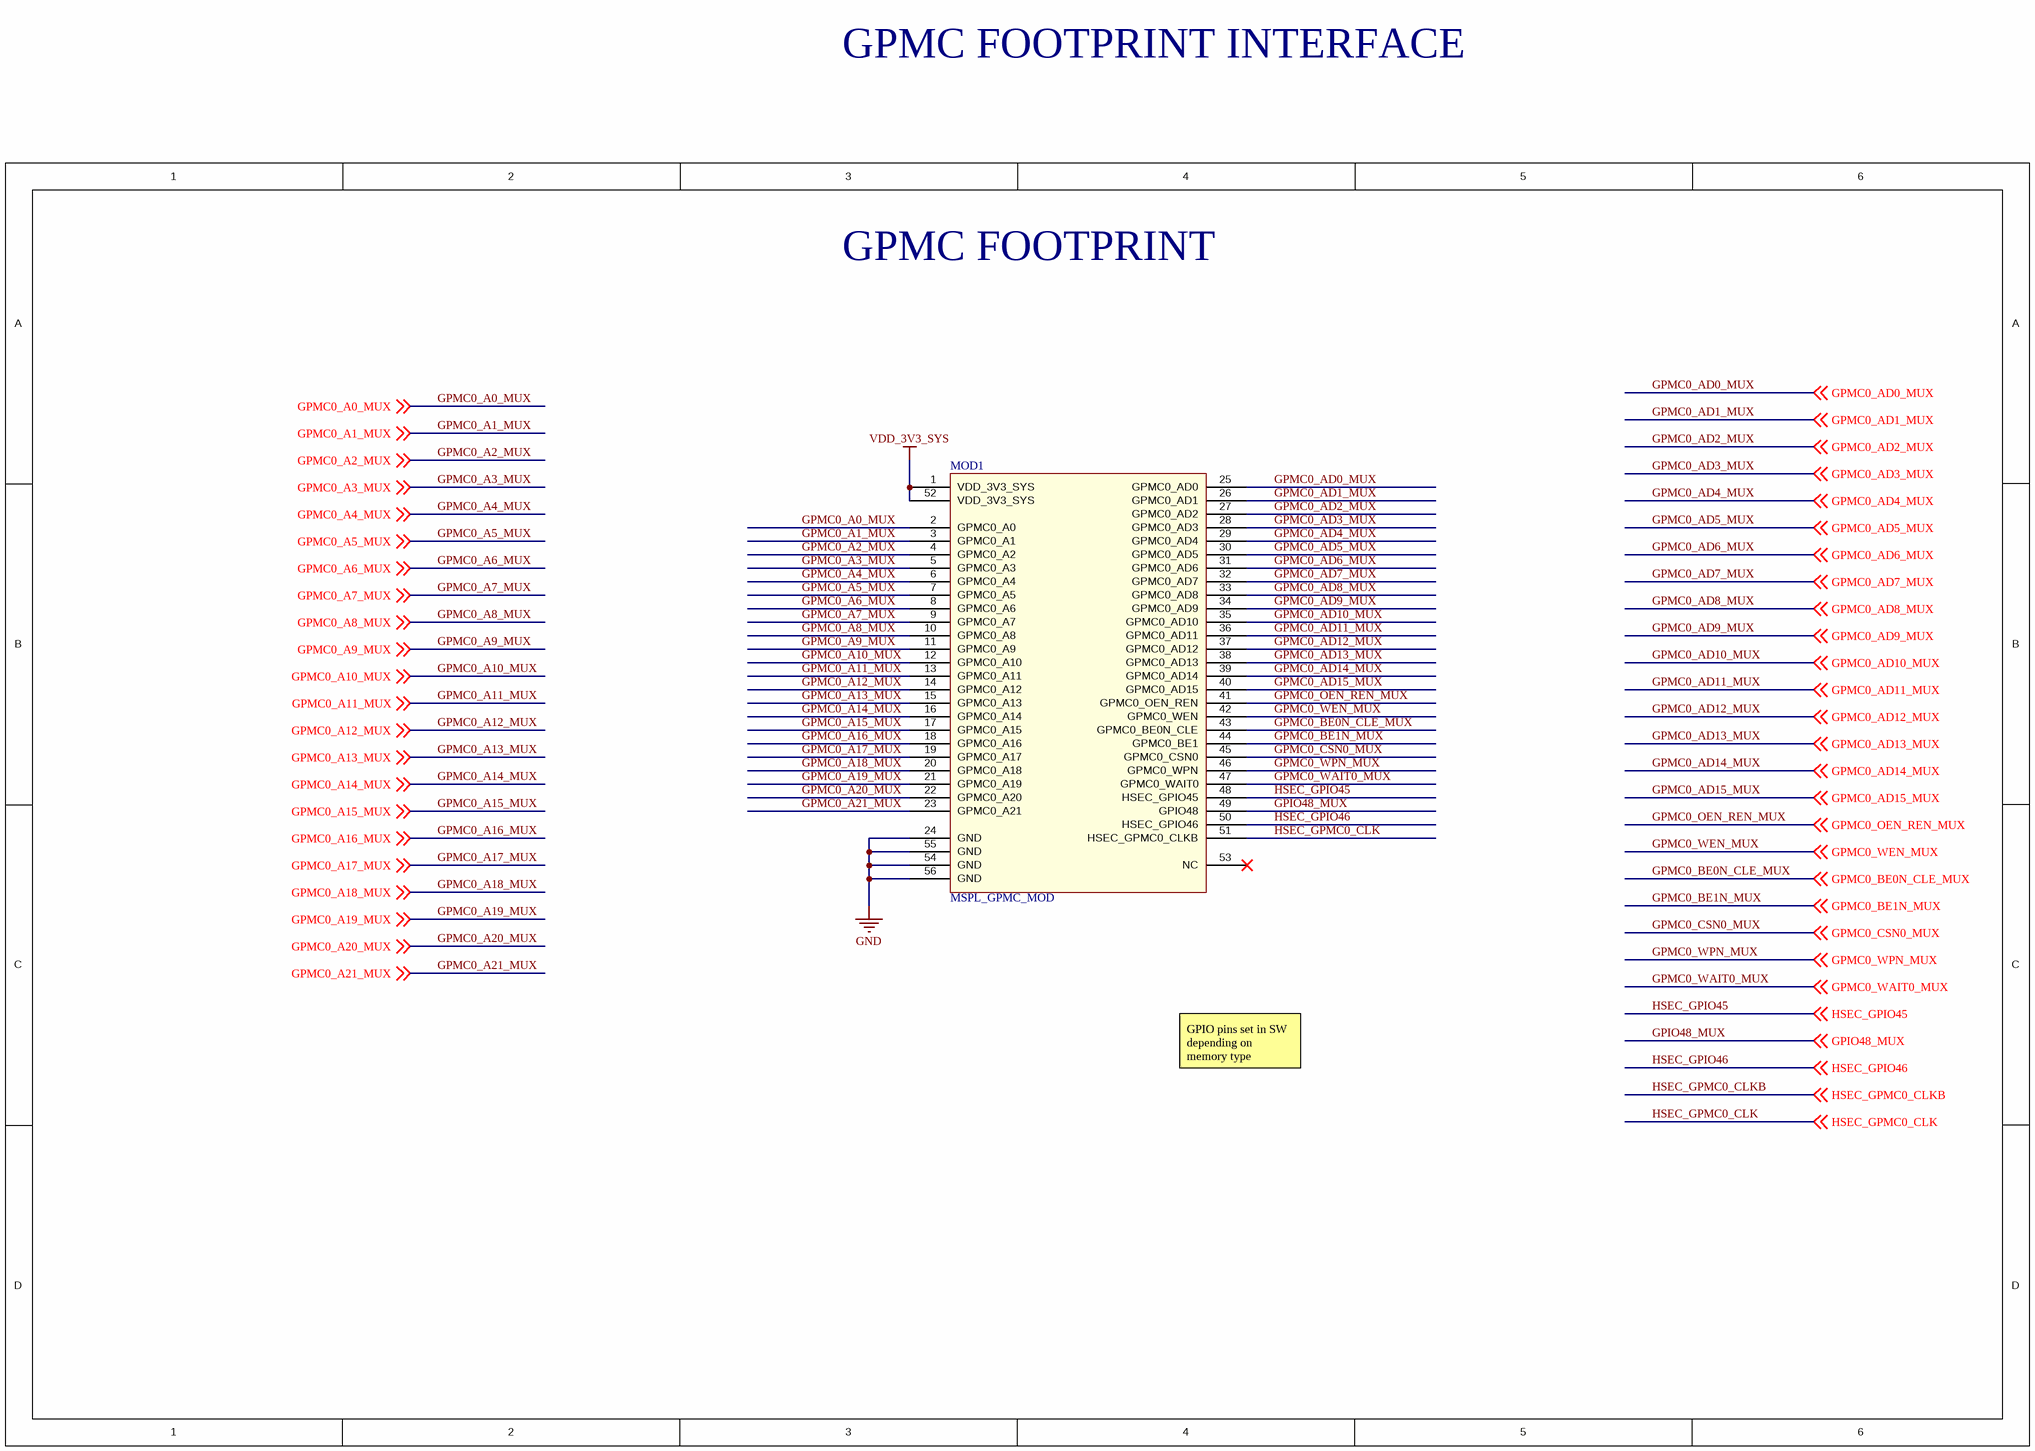
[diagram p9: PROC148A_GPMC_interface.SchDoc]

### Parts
MOD1  MSPL_GPMC_MOD  [MSPL_GPMC_MOD]

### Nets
GND: MOD1.24(GND) MOD1.54(GND) MOD1.55(GND) MOD1.56(GND)
VDD_3V3_SYS: MOD1.1(VDD_3V3_SYS) MOD1.52(VDD_3V3_SYS)
GPIO48_MUX: MOD1.49(GPIO48) ; off-sheet GPIO48_MUX
GPMC0_A0_MUX: MOD1.2(GPMC0_A0) ; off-sheet GPMC0_A0_MUX
GPMC0_A1_MUX: MOD1.3(GPMC0_A1) ; off-sheet GPMC0_A1_MUX
GPMC0_A2_MUX: MOD1.4(GPMC0_A2) ; off-sheet GPMC0_A2_MUX
GPMC0_A3_MUX: MOD1.5(GPMC0_A3) ; off-sheet GPMC0_A3_MUX
GPMC0_A4_MUX: MOD1.6(GPMC0_A4) ; off-sheet GPMC0_A4_MUX
GPMC0_A5_MUX: MOD1.7(GPMC0_A5) ; off-sheet GPMC0_A5_MUX
GPMC0_A6_MUX: MOD1.8(GPMC0_A6) ; off-sheet GPMC0_A6_MUX
GPMC0_A7_MUX: MOD1.9(GPMC0_A7) ; off-sheet GPMC0_A7_MUX
GPMC0_A8_MUX: MOD1.10(GPMC0_A8) ; off-sheet GPMC0_A8_MUX
GPMC0_A9_MUX: MOD1.11(GPMC0_A9) ; off-sheet GPMC0_A9_MUX
GPMC0_A10_MUX: MOD1.12(GPMC0_A10) ; off-sheet GPMC0_A10_MUX
GPMC0_A11_MUX: MOD1.13(GPMC0_A11) ; off-sheet GPMC0_A11_MUX
GPMC0_A12_MUX: MOD1.14(GPMC0_A12) ; off-sheet GPMC0_A12_MUX
GPMC0_A13_MUX: MOD1.15(GPMC0_A13) ; off-sheet GPMC0_A13_MUX
GPMC0_A14_MUX: MOD1.16(GPMC0_A14) ; off-sheet GPMC0_A14_MUX
GPMC0_A15_MUX: MOD1.17(GPMC0_A15) ; off-sheet GPMC0_A15_MUX
GPMC0_A16_MUX: MOD1.18(GPMC0_A16) ; off-sheet GPMC0_A16_MUX
GPMC0_A17_MUX: MOD1.19(GPMC0_A17) ; off-sheet GPMC0_A17_MUX
GPMC0_A18_MUX: MOD1.20(GPMC0_A18) ; off-sheet GPMC0_A18_MUX
GPMC0_A19_MUX: MOD1.21(GPMC0_A19) ; off-sheet GPMC0_A19_MUX
GPMC0_A20_MUX: MOD1.22(GPMC0_A20) ; off-sheet GPMC0_A20_MUX
GPMC0_A21_MUX: MOD1.23(GPMC0_A21) ; off-sheet GPMC0_A21_MUX
GPMC0_AD0_MUX: MOD1.25(GPMC0_AD0) ; off-sheet GPMC0_AD0_MUX
GPMC0_AD1_MUX: MOD1.26(GPMC0_AD1) ; off-sheet GPMC0_AD1_MUX
GPMC0_AD2_MUX: MOD1.27(GPMC0_AD2) ; off-sheet GPMC0_AD2_MUX
GPMC0_AD3_MUX: MOD1.28(GPMC0_AD3) ; off-sheet GPMC0_AD3_MUX
GPMC0_AD4_MUX: MOD1.29(GPMC0_AD4) ; off-sheet GPMC0_AD4_MUX
GPMC0_AD5_MUX: MOD1.30(GPMC0_AD5) ; off-sheet GPMC0_AD5_MUX
GPMC0_AD6_MUX: MOD1.31(GPMC0_AD6) ; off-sheet GPMC0_AD6_MUX
GPMC0_AD7_MUX: MOD1.32(GPMC0_AD7) ; off-sheet GPMC0_AD7_MUX
GPMC0_AD8_MUX: MOD1.33(GPMC0_AD8) ; off-sheet GPMC0_AD8_MUX
GPMC0_AD9_MUX: MOD1.34(GPMC0_AD9) ; off-sheet GPMC0_AD9_MUX
GPMC0_AD10_MUX: MOD1.35(GPMC0_AD10) ; off-sheet GPMC0_AD10_MUX
GPMC0_AD11_MUX: MOD1.36(GPMC0_AD11) ; off-sheet GPMC0_AD11_MUX
GPMC0_AD12_MUX: MOD1.37(GPMC0_AD12) ; off-sheet GPMC0_AD12_MUX
GPMC0_AD13_MUX: MOD1.38(GPMC0_AD13) ; off-sheet GPMC0_AD13_MUX
GPMC0_AD14_MUX: MOD1.39(GPMC0_AD14) ; off-sheet GPMC0_AD14_MUX
GPMC0_AD15_MUX: MOD1.40(GPMC0_AD15) ; off-sheet GPMC0_AD15_MUX
GPMC0_BE0N_CLE_MUX: MOD1.43(GPMC0_BE0N_CLE) ; off-sheet GPMC0_BE0N_CLE_MUX
GPMC0_BE1N_MUX: MOD1.44(GPMC0_BE1) ; off-sheet GPMC0_BE1N_MUX
GPMC0_CSN0_MUX: MOD1.45(GPMC0_CSN0) ; off-sheet GPMC0_CSN0_MUX
GPMC0_OEN_REN_MUX: MOD1.41(GPMC0_OEN_REN) ; off-sheet GPMC0_OEN_REN_MUX
GPMC0_WAIT0_MUX: MOD1.47(GPMC0_WAIT0) ; off-sheet GPMC0_WAIT0_MUX
GPMC0_WEN_MUX: MOD1.42(GPMC0_WEN) ; off-sheet GPMC0_WEN_MUX
GPMC0_WPN_MUX: MOD1.46(GPMC0_WPN) ; off-sheet GPMC0_WPN_MUX
HSEC_GPIO45: MOD1.48(HSEC_GPIO45) ; off-sheet HSEC_GPIO45
HSEC_GPIO46: MOD1.50(HSEC_GPIO46) ; off-sheet HSEC_GPIO46
HSEC_GPMC0_CLK: MOD1.51(HSEC_GPMC0_CLKB) ; off-sheet HSEC_GPMC0_CLK

Not connected (* = marked no-connect by the designer): MOD1 53(NC)*

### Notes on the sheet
- GPMC FOOTPRINT INTERFACE
- GPMC FOOTPRINT
- GPIO pins set in SW depending on memory type

## Sheet PROC148A_JTAG_TRACE.SchDoc
size 431 x 279 mm; Date: Not shown in title block; ApprovedBy: Not shown in title block; CheckedBy: Not shown in title block; Author: Not shown in title block; CompanyName: Not shown in title block; Engineer: Not shown in title block; Organization: Not shown in title block; Address1: Not shown in title block; Address2: Not shown in title block; Address3: Not shown in title block; Address4: Not shown in title block; DocumentNumber: 1; Revision: Use project parameter SCH_Rev; SheetNumber: 8; SheetTotal: 9; PageSetup: Record=PageOptions¦CenterHorizontal=True¦CenterVertical=True¦PrintScale=1.00¦XCorrection=1.00¦YCorrection=1.00¦PrintKind=0¦BorderSize=5000000¦LeftOffset=0¦BottomOffset=0¦Orientation=2¦PaperLength=1000¦PaperWidth=1000¦Scale=100¦PaperSource=15¦PrintQuality=600¦MediaType=1¦DitherType=10¦PaperKind=Letter¦PrintScaleMode=1
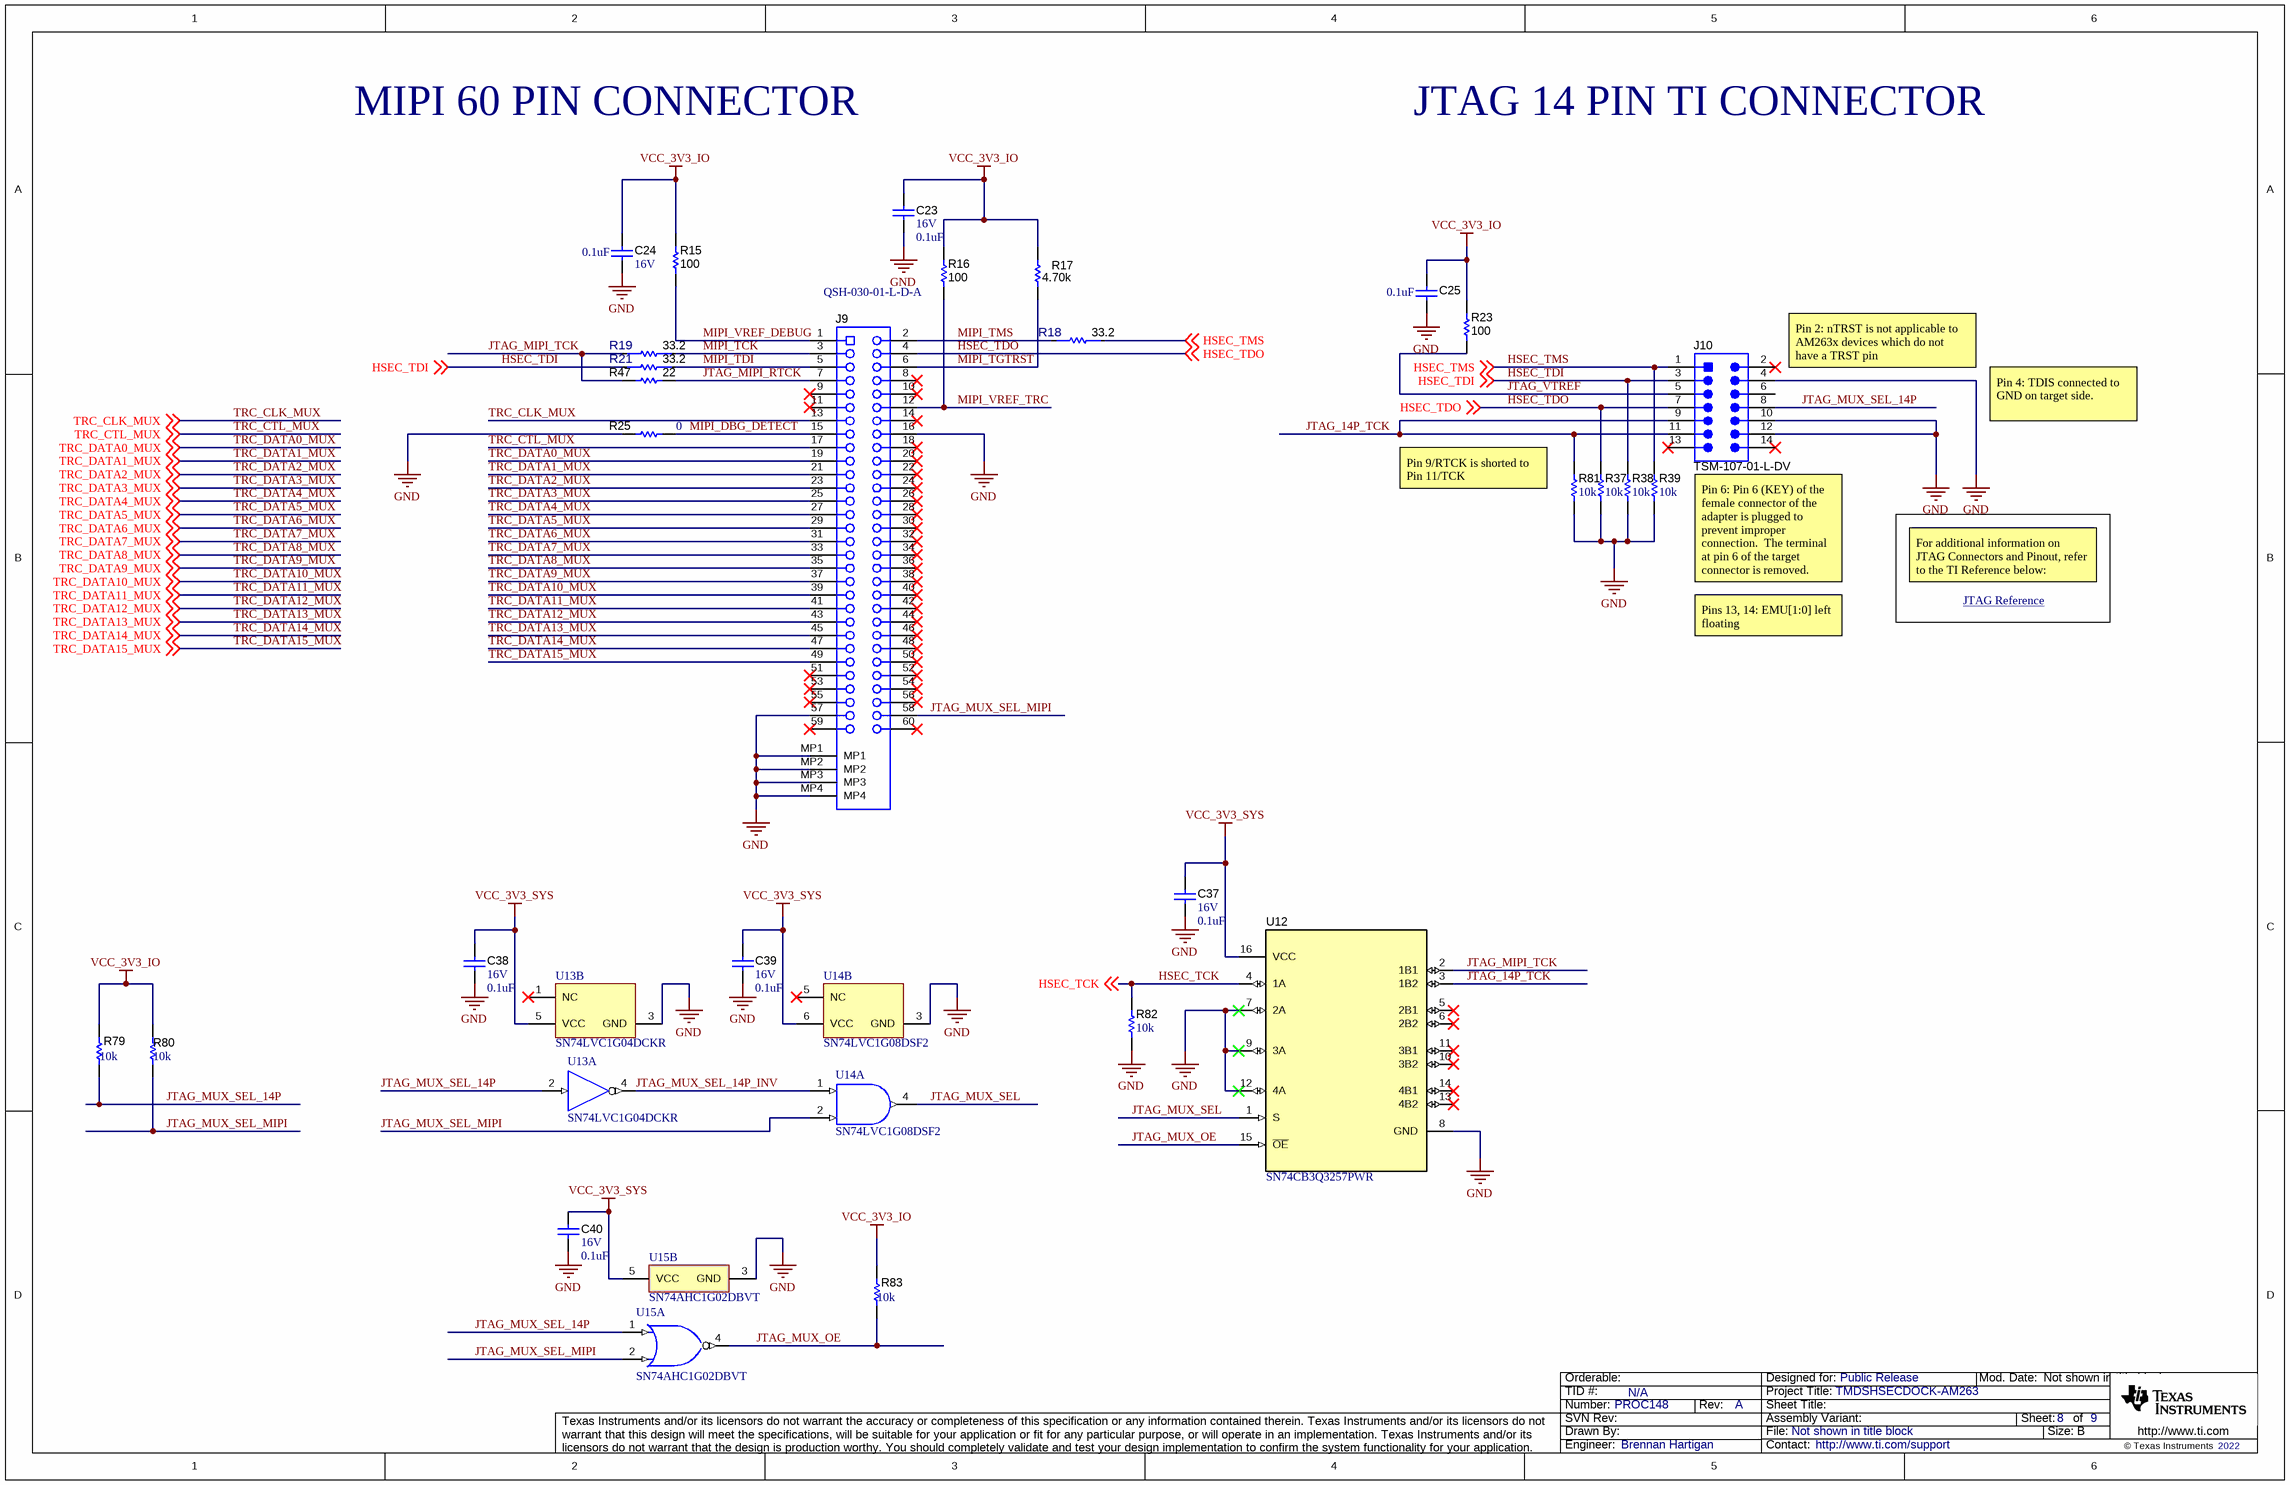
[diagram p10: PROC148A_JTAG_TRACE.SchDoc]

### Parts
C23  VDC_V: 16V  ValueDisplayed: 0.1uF  [0201_033]  (hidden comment: GRM033R61C104KE84D)
C24  VDC_V: 16V  ValueDisplayed: 0.1uF  [0201_033]  (hidden comment: GRM033R61C104KE84D)
C25  ValueDisplayed: 0.1uF  [0201_033]  (hidden comment: GRM033R61C104KE84D)
C37  VDC_V: 16V  ValueDisplayed: 0.1uF  [0201_033]  (hidden comment: GRM033R61C104KE84D)
C38  VDC_V: 16V  ValueDisplayed: 0.1uF  [0201_033]  (hidden comment: GRM033R61C104KE84D)
C39  VDC_V: 16V  ValueDisplayed: 0.1uF  [0201_033]  (hidden comment: GRM033R61C104KE84D)
C40  VDC_V: 16V  ValueDisplayed: 0.1uF  [0201_033]  (hidden comment: GRM033R61C104KE84D)
J9  PartNumber: QSH-030-01-L-D-A  [Samtec_QSH-030-01-X-D-A]  (hidden comment: Receptacle_30x2_4MP_LeftRight)
J10  TSM-107-01-L-DV  [Samtec_TSM-107-01-x-DV]
R15  ValueDisplayed: 100  [0201]  (hidden comment: CRCW0201100RFKED)
R16  ValueDisplayed: 100  [0201]  (hidden comment: CRCW0201100RFKED)
R17  ValueDisplayed: 4.70k  [0201_033]  (hidden comment: CRCW02014K70FKED)
R18  Res_ohm: 33.2  [FP-ERJ-1GNF33R2C_0201-IPC_B]  (hidden comment: ERJ-1GNF33R2C)
R19  Res_ohm: 33.2  [FP-ERJ-1GNF33R2C_0201-IPC_B]  (hidden comment: ERJ-1GNF33R2C)
R21  Res_ohm: 33.2  [FP-ERJ-1GNF33R2C_0201-IPC_B]  (hidden comment: ERJ-1GNF33R2C)
R23  ValueDisplayed: 100  [0201]  (hidden comment: CRCW0201100RFKED)
R25  ValueDisplayed: 0  [0201]  (hidden comment: CRCW02010000Z0ED)
R37  ValueDisplayed: 10k  [0402]  (hidden comment: CRCW040210K0JNED)
R38  ValueDisplayed: 10k  [0402]  (hidden comment: CRCW040210K0JNED)
R39  ValueDisplayed: 10k  [0402]  (hidden comment: CRCW040210K0JNED)
R47  ValueDisplayed: 22  [0201]  (hidden comment: ERJ-1GNJ220C)
R79  ValueDisplayed: 10k  [0402]  (hidden comment: CRCW040210K0JNED)
R80  ValueDisplayed: 10k  [0402]  (hidden comment: CRCW040210K0JNED)
R81  ValueDisplayed: 10k  [0402]  (hidden comment: CRCW040210K0JNED)
R82  ValueDisplayed: 10k  [0402]  (hidden comment: CRCW040210K0JNED)
R83  ValueDisplayed: 10k  [0402]  (hidden comment: CRCW040210K0JNED)
U12  SN74CB3Q3257PWR  [PW0016A_L]
U13  SN74LVC1G04DCKR  [DCK0005A_N]  (parts A,B of 2)
U14  SN74LVC1G08DSF2  [DSF0006A]  (parts A,B of 2)
U15  SN74AHC1G02DBVT  [DBV0005A_N]  (parts A,B of 2)

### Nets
GND: C23.2 C24.2 C25.2 C37.2 C38.2 C39.2 C40.2 J9.16 J9.57 J9.MP1 J9.MP2 J9.MP3 J9.MP4 J10.4 J10.10 J10.12 R25.1 R37.1 R38.1 R39.1 R81.1 R82.1 U12.7(2A) U12.8(GND) U12.9(3A) U12.12(4A) U13.3(GND) U14.3(GND) U15.3(GND)
VCC_3V3_IO: C23.1 C24.1 C25.1 R15.2 R16.2 R17.2 R23.2 R79.2 R80.2 R83.2
VCC_3V3_SYS: C37.1 C38.1 C39.1 C40.1 U12.16(VCC) U13.5(VCC) U14.6(VCC) U15.5(VCC)
HSEC_TCK: R82.2 U12.4(1A) ; off-sheet HSEC_TCK
HSEC_TDI: J10.3 R21.2 R38.2 ; off-sheet HSEC_TDI
HSEC_TDO: J9.4 J10.7 R37.2 ; off-sheet HSEC_TDO
HSEC_TMS: J10.1 R18.1 R39.2 ; off-sheet HSEC_TMS
JTAG_14P_TCK: J10.9 J10.11 R81.2 U12.3(1B2)
JTAG_MIPI_RTCK: J9.7 R47.2
JTAG_MIPI_TCK: R19.2 R47.1 U12.2(1B1)
JTAG_MUX_OE: R83.1 U12.15(~{OE}) U15.4(Y)
JTAG_MUX_SEL: U12.1(S) U14.4(Y)
JTAG_MUX_SEL_14P: J10.8 R79.1 U13.2(A) U15.1(A)
JTAG_MUX_SEL_14P_INV: U13.4(Y) U14.1(A)
JTAG_MUX_SEL_MIPI: J9.58 R80.1 U14.2(B) U15.2(B)
JTAG_VTREF: J10.5 R23.1
MIPI_DBG_DETECT: J9.15 R25.2
MIPI_TCK: J9.3 R19.1
MIPI_TDI: J9.5 R21.1
MIPI_TGTRST: J9.6 R17.1
MIPI_TMS: J9.2 R18.2
MIPI_VREF_DEBUG: J9.1 R15.1
MIPI_VREF_TRC: J9.12 R16.1
TRC_CLK_MUX: J9.13 ; off-sheet TRC_CLK_MUX
TRC_CTL_MUX: J9.17 ; off-sheet TRC_CTL_MUX
TRC_DATA0_MUX: J9.19 ; off-sheet TRC_DATA0_MUX
TRC_DATA1_MUX: J9.21 ; off-sheet TRC_DATA1_MUX
TRC_DATA2_MUX: J9.23 ; off-sheet TRC_DATA2_MUX
TRC_DATA3_MUX: J9.25 ; off-sheet TRC_DATA3_MUX
TRC_DATA4_MUX: J9.27 ; off-sheet TRC_DATA4_MUX
TRC_DATA5_MUX: J9.29 ; off-sheet TRC_DATA5_MUX
TRC_DATA6_MUX: J9.31 ; off-sheet TRC_DATA6_MUX
TRC_DATA7_MUX: J9.33 ; off-sheet TRC_DATA7_MUX
TRC_DATA8_MUX: J9.35 ; off-sheet TRC_DATA8_MUX
TRC_DATA9_MUX: J9.37 ; off-sheet TRC_DATA9_MUX
TRC_DATA10_MUX: J9.39 ; off-sheet TRC_DATA10_MUX
TRC_DATA11_MUX: J9.41 ; off-sheet TRC_DATA11_MUX
TRC_DATA12_MUX: J9.43 ; off-sheet TRC_DATA12_MUX
TRC_DATA13_MUX: J9.45 ; off-sheet TRC_DATA13_MUX
TRC_DATA14_MUX: J9.47 ; off-sheet TRC_DATA14_MUX
TRC_DATA15_MUX: J9.49 ; off-sheet TRC_DATA15_MUX

Not connected (* = marked no-connect by the designer): J9 8* 9* 10* 11* 14* 18* 20* 22* 24* 26* 28* 30* 32* 34* 36* 38* 40* 42* 44* 46* 48* 50* 51* 52* 53* 54* 55* 56* 59* 60*; J10 2* 6 13* 14*; U12 5(2B1)* 6(2B2)* 10(3B2)* 11(3B1)* 13(4B2)* 14(4B1)*; U13 1(NC)*; U14 5(NC)*

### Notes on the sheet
- MIPI 60 PIN CONNECTOR
- JTAG 14 PIN TI CONNECTOR
- (near J10) Pin 2: nTRST is not applicable to AM263x devices which do not have a TRST pin
- Pin 4: TDIS connected to GND on target side.
- (near R81) Pin 9/RTCK is shorted to Pin 11/TCK
- Pins 13, 14: EMU[1:0] left floating
- Pin 6: Pin 6 (KEY) of the female connector of the adapter is plugged to prevent improper connection.  The terminal at pin 6 of the target connector is removed.
- For additional information on JTAG Connectors and Pinout, refer to the TI Reference below:
- JTAG Reference <https://software-dl.ti.com/ccs/esd/documents/xdsdebugprobes/emu_jtag_connectors.html>

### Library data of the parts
C23 C24 C37-C40 = CMP-0009717-2: as C11-C22 on sheet PROC148A_HSECMUX
C25 = CMP-0009717-2: CAP, CERM, 0.1 uF, 16 V, +/- 10%, X5R, 0201; Manufacturer: MuRata; TaMin_C: -55°C; Polarized: N; SizeAreaWB_mm2: 2.08; Value1: Unknown; U/M: EA; Value: 0.1uF; TaMax_C: 85°C; SizeZ_mm: 0.33; SizeX_mm: 0.6; SizeY_mm: 0.3; Cap_Case: 0201; Value2: 16V; SizeArea_mm2: 0.18; Cap_F: 100nF; AEC Category: Q200
J9 = CMP-0075524-1: Receptacle, 0.5 mm, 30x2, Gold, TH; Manufacturer: Samtec; Pitch_mm: 0.5; Gender: Female; Shrouded: N; Row_Count: 2; RowSpacing_mm: 5.73; Green_Lifecycle: Active; Green_REACh: Passed; CNHeader: False
J10 = CMP-0075611-2: Header, 2.54mm, 7x2, Gold, SMT; Manufacturer: Samtec; Pitch_mm: 2.54; Gender: Male; Cert_CSA: Y; Current_A: 5.4A; Shrouded: N; Row_Count: 2
R15 R16 R23 = CMP-0083836-1: RES, 100, 1%, 0.05 W, 0201; Manufacturer: Vishay-Semiconductor; Value_Code: 100R; SizeAreaWB_mm2: 2.08; SizeArea_mm2: 0.18; AEC Qualified: N; AEC Category: Q200; Value: 100; SizeZ_mm: 0.26; EIA_Code: E96; TempCo: 100 ppm/C; Power_W: 50mW; SizeY_mm: 0.3; Value2: 0.05W; SizeX_mm: 0.6
R17 = CMP-0027280-3: RES, 4.70 k, 1%, 0.05 W, 0201; Manufacturer: Vishay-Dale; Power_W: 50mW; TempCo: 100 ppm/C; Value_Code: 4k70; Value: 4.70k; Res_ohm: 4.7k; SizeX_mm: 0.6; SizeY_mm: 0.3; SizeZ_mm: 0.33; Value2: 0.05W; SizeArea_mm2: 0.18; AEC Qualified: N; VDC_V: 30V; AEC Category: Q200
R18 R19 R21 = CMP-0089575-2: Res Thick Film 0201 33.2 Ohm 1% 0.05W(1/20W) ±200ppm/C Pad SMD Automotive T/R; Manufacturer: Panasonic; TempCo: 200ppm/°C; VDC_V: 25V; AEC Qualified: Yes; SizeZ_mm: 0.26mm; Power_W: 50mW; AEC Grade: Grade 1; Value: 33.2
R25 = CMP-0027008-4: RES, 0, 5%, 0.05 W, 0201; Manufacturer: Vishay-Dale; Power_W: 50mW; TempCo: ppm/C; Value_Code: 0000; Value: 0; EIA_Code: E24; SizeX_mm: 0.6; SizeY_mm: 0.3; SizeZ_mm: 0.26; Value2: 0.05W; SizeArea_mm2: 0.18; AEC Qualified: N; AEC Category: Q200
R37-R39 R79-R83 = CMP-0026825-5: as R13 on sheet PROC148A_HSECMUX
R47 = CMP-0027015-3: RES, 22, 5%, 0.05 W, AEC-Q200 Grade 1, 0201; Manufacturer: Panasonic; Power_W: 50mW; TempCo: 200 ppm/C; Value_Code: 22R0; U/M: EA; Value: 22; EIA_Code: E24; SizeX_mm: 0.6; SizeY_mm: 0.3; SizeZ_mm: 0.26; Value2: 0.05W; SizeArea_mm2: 0.18; AEC Qualified: Y; AEC Grade: 1; AEC Category: Q200
U12 = CMP-0076540-1: 4-Bit One-of-2 FET Multiplexer/Demultiplexer 2.5-V/3.3-V Low-Voltage, High-Bandwidth Bus Switch, PW0016A (TSSOP-16); Manufacturer: Texas Instruments; SizeAreaWB_mm2: 58.8; SizeArea_mm2: 32.0; SizeZ_mm: 1.2; SizeY_mm: 5.0; U/M: EA; CompType: IC; SizeX_mm: 6.4
U13 = CMP-0051684-3: Single Inverter, DCK0005A, LARGE T&R; Manufacturer: Texas Instruments; Input Type: CMOS/TTL; Output Drive (IOL/IOH)(Max)(mA): 32/-32; Sub-Family: Inverting Buffer/Driver; VCC(Min)(V): 1.65; Bits(#): 1; Schmitt Trigger: No; Technology Family: LVC; Rating: Catalog; ICC @ Nom Voltage(Max)(mA): 0.01; tpd @ Nom Voltage(Max)(ns): 7.5,5.2,4.2,3.7; Voltage(Nom)(V): 1.8,2.5,3.3,5; F @ Nom Voltage(Max)(Mhz): 150; Output Type: CMOS; VCC(Max)(V): 5.5; Logic: Inverting; AEC Category: Q200; AEC Qualified: N; CompType: IC; SizeAreaWB_mm2: 9.3; SizeArea_mm2: 4.2; SizeX_mm: 2.1; SizeY_mm: 2.0; SizeZ_mm: 1.1
U14 = CMP-0051419-5: Single 2-Input Positive-AND Gate, DSF0006A, LARGE T&R; Manufacturer: Texas Instruments; Output Type: CMOS; Bits(#): 1; Input Type: CMOS/TTL; Technology Family: LVC; Schmitt Trigger: No; VCC(Max)(V): 5.5; Gate Type: AND; Rating: Catalog; Output Drive (IOL/IOH)(Max)(mA): 32/-32; ICC @ Nom Voltage(Max)(mA): 0.01; VCC(Min)(V): 1.65; F @ Nom Voltage(Max)(Mhz): 150; Logic: True; Voltage(Nom)(V): 1.8,2.5,3.3,5; tpd @ Nom Voltage(Max)(ns): 4.5,6,4,5; AEC Category: Q200; AEC Qualified: N; CompType: IC
U15 = CMP-0051529-2: Single 2-Input Positive-NOR Gate, DBV0005A (SOT-23-5); Manufacturer: Texas Instruments; Rating: Catalog; Output Drive (IOL/IOH)(Max)(mA): 50/-50; ICC @ Nom Voltage(Max)(mA): 0.01; Bits(#): 1; Output Type: CMOS; Logic: True; Voltage(Nom)(V): 3.3,5; 3-State Output: No; VCC(Max)(V): 5.5; Gate Type: NOR; F @ Nom Voltage(Max)(Mhz): 75; VCC(Min)(V): 2; tpd @ Nom Voltage(Max)(ns): 11.4,7.5; AEC Category: Q200; AEC Qualified: N; CompType: IC; SizeAreaWB_mm2: 14.82; SizeArea_mm2: 8.12; SizeX_mm: 2.8; SizeY_mm: 2.9; SizeZ_mm: 1.45

## Sheet PROC148A_Hardware.SchDoc
size 431 x 279 mm; Date: Not shown in title block; ApprovedBy: Not shown in title block; CheckedBy: Not shown in title block; Author: Not shown in title block; CompanyName: Not shown in title block; Engineer: Not shown in title block; Organization: Not shown in title block; Address1: Not shown in title block; Address2: Not shown in title block; Address3: Not shown in title block; Address4: Not shown in title block; DocumentNumber: 3; Revision: Use project parameter SCH_Rev; SheetNumber: 9; SheetTotal: 9; PageSetup: Record=PageOptions¦CenterHorizontal=True¦CenterVertical=True¦PrintScale=1.00¦XCorrection=1.00¦YCorrection=1.00¦PrintKind=0¦BorderSize=5000000¦LeftOffset=0¦BottomOffset=0¦Orientation=2¦PaperLength=1000¦PaperWidth=1000¦Scale=100¦PaperSource=15¦PrintQuality=600¦MediaType=1¦DitherType=10¦PaperKind=Letter¦PrintScaleMode=1
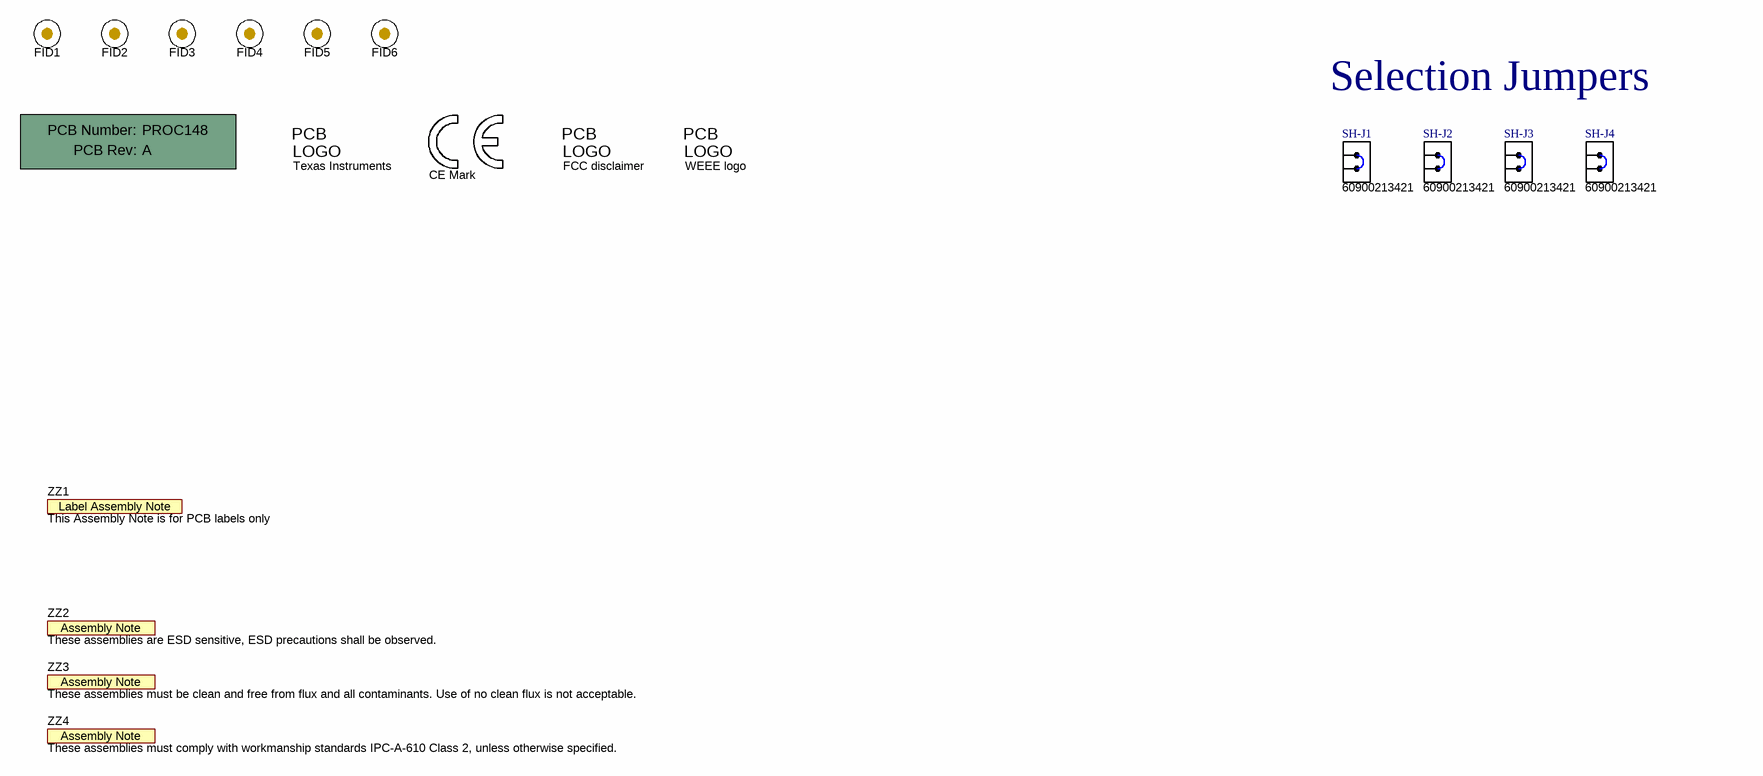
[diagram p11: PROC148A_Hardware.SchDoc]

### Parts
!PCB1  Printed Circuit Board  (value not drawn)  (mechanical)
FID1  Fiducial  [Fiducial10-20]  (value not drawn)
FID2  Fiducial  [Fiducial10-20]  (value not drawn)
FID3  Fiducial  [Fiducial10-20]  (value not drawn)
FID4  Fiducial  [Fiducial10-20]  (value not drawn)
FID5  Fiducial  [Fiducial10-20]  (value not drawn)
FID6  Fiducial  [Fiducial10-20]  (value not drawn)
Logo1  CE Mark  [CE_Mark_5mm]  (no BOM)
Logo2  Texas Instruments  [TI_Stacked_Overlay_Small]  (no BOM)
Logo3  FCC disclaimer  [FCC_disclaimer]  (no BOM)
Logo4  WEEE logo  [WEEE_Minimum]  (no BOM)
SH-J1  60900213421  [Wurth_60900213421]
SH-J2  60900213421  [Wurth_60900213421]
SH-J3  60900213421  [Wurth_60900213421]
SH-J4  60900213421  [Wurth_60900213421]
ZZ1  This Assembly Note is for PCB labels only  [AssemblyNoteLabel]  (no BOM)
ZZ2  These assemblies are ESD sensitive, ESD precautions shall be observed.  [AssemblyNote]  (no BOM)
ZZ3  These assemblies must be clean and free from flux and all contaminants. Use of no clean flux is not acceptable.  [AssemblyNote]  (no BOM)
ZZ4  These assemblies must comply with workmanship standards IPC-A-610 Class 2, unless otherwise specified.  [AssemblyNote]  (no BOM)

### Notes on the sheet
- Selection Jumpers

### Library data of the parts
!PCB1 = CMP-0003618-2: Manufacturer: Any; PartNumber: PROC148
FID1-FID6 = CMP-0077181-1: Fiducial mark.  There is nothing to buy or mount.
Logo1 = CMP-0074844-1: SymbolCreator: a0412235
Logo2 = CMP-0074838-1: Texas Instrument Corporate Signature; SymbolCreator: a0412235; Lib Reference: TI_Logo; Library Reference: Logo
Logo3 = CMP-0074847-1: FCC_disclaimer; Library Reference: Logo
Logo4 = CMP-0074769-1
SH-J1-SH-J4 = CMP-0003761-2: Shunt, 2.54mm, Gold, Black; Manufacturer: Wurth Elektronik
ZZ1 = CMP-0003616-3
ZZ2 = CMP-0077236-1
ZZ3 = CMP-0077237-1
ZZ4 = CMP-0077238-1

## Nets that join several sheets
GND: PROC148A_PWR (35 pins), PROC148A_HSEC (104 pins), PROC148A_CAN_LIN (17 pins), PROC148A_HSECMUX (22 pins), PROC148A_PSRAM (C9.2 C10.2 U3.D1 U3.E6), PROC148A_GPMC_interface (MOD1.24 MOD1.54 MOD1.55 MOD1.56), PROC148A_JTAG_TRACE (29 pins)
VCC_3V3_IO: PROC148A_PWR (FB4.2), PROC148A_CAN_LIN (R85.2 R86.2 R87.1 R90.1), PROC148A_HSECMUX (26 pins), PROC148A_PSRAM (6 pins), PROC148A_JTAG_TRACE (10 pins)
VCC_3V3_SYS: PROC148A_PWR (5 pins), PROC148A_HSEC (11 pins), PROC148A_PSRAM (FB3.1), PROC148A_JTAG_TRACE (8 pins)
VMAIN: PROC148A_PWR (7 pins), PROC148A_HSEC (10 pins), PROC148A_CAN_LIN (FB5.1 FB6.1)
GPIO48_MUX: PROC148A_HSECMUX (U6.19), PROC148A_PSRAM (R78.1 U3.A6), PROC148A_GPMC_interface (MOD1.49)
GPMC0_A0_MUX: PROC148A_HSECMUX (U5.34), PROC148A_PSRAM (U3.A3), PROC148A_GPMC_interface (MOD1.2)
GPMC0_A1_MUX: PROC148A_HSECMUX (U5.36), PROC148A_PSRAM (U3.A4), PROC148A_GPMC_interface (MOD1.3)
GPMC0_A2_MUX: PROC148A_HSECMUX (U5.38), PROC148A_PSRAM (U3.A5), PROC148A_GPMC_interface (MOD1.4)
GPMC0_A3_MUX: PROC148A_HSECMUX (U5.39), PROC148A_PSRAM (U3.B3), PROC148A_GPMC_interface (MOD1.5)
GPMC0_A4_MUX: PROC148A_HSECMUX (U5.41), PROC148A_PSRAM (U3.B4), PROC148A_GPMC_interface (MOD1.6)
GPMC0_A5_MUX: PROC148A_HSECMUX (U7.19), PROC148A_PSRAM (U3.C3), PROC148A_GPMC_interface (MOD1.7)
GPMC0_A6_MUX: PROC148A_HSECMUX (U7.21), PROC148A_PSRAM (U3.C4), PROC148A_GPMC_interface (MOD1.8)
GPMC0_A7_MUX: PROC148A_HSECMUX (U7.23), PROC148A_PSRAM (U3.D4), PROC148A_GPMC_interface (MOD1.9)
GPMC0_A8_MUX: PROC148A_HSECMUX (U7.25), PROC148A_PSRAM (U3.H2), PROC148A_GPMC_interface (MOD1.10)
GPMC0_A9_MUX: PROC148A_HSECMUX (U7.27), PROC148A_PSRAM (U3.H3), PROC148A_GPMC_interface (MOD1.11)
GPMC0_A10_MUX: PROC148A_HSECMUX (U7.29), PROC148A_PSRAM (U3.H4), PROC148A_GPMC_interface (MOD1.12)
GPMC0_A11_MUX: PROC148A_HSECMUX (U7.39), PROC148A_PSRAM (U3.H5), PROC148A_GPMC_interface (MOD1.13)
GPMC0_A12_MUX: PROC148A_HSECMUX (U7.41), PROC148A_PSRAM (U3.G3), PROC148A_GPMC_interface (MOD1.14)
GPMC0_A13_MUX: PROC148A_HSECMUX (U4.19), PROC148A_PSRAM (U3.G4), PROC148A_GPMC_interface (MOD1.15)
GPMC0_A14_MUX: PROC148A_HSECMUX (U4.21), PROC148A_PSRAM (U3.F3), PROC148A_GPMC_interface (MOD1.16)
GPMC0_A15_MUX: PROC148A_HSECMUX (U4.23), PROC148A_PSRAM (U3.F4), PROC148A_GPMC_interface (MOD1.17)
GPMC0_A16_MUX: PROC148A_HSECMUX (U4.25), PROC148A_PSRAM (U3.E4), PROC148A_GPMC_interface (MOD1.18)
GPMC0_A17_MUX: PROC148A_HSECMUX (U4.27), PROC148A_PSRAM (U3.D3), PROC148A_GPMC_interface (MOD1.19)
GPMC0_A18_MUX: PROC148A_HSECMUX (U4.29), PROC148A_PSRAM (U3.H1), PROC148A_GPMC_interface (MOD1.20)
GPMC0_A19_MUX: PROC148A_HSECMUX (U4.32), PROC148A_PSRAM (U3.G2), PROC148A_GPMC_interface (MOD1.21)
GPMC0_A20_MUX: PROC148A_HSECMUX (U4.34), PROC148A_PSRAM (U3.H6), PROC148A_GPMC_interface (MOD1.22)
GPMC0_A21_MUX: PROC148A_HSECMUX (U4.36), PROC148A_PSRAM (U3.E3), PROC148A_GPMC_interface (MOD1.23)
GPMC0_AD0_MUX: PROC148A_HSECMUX (U6.21), PROC148A_PSRAM (R12.2), PROC148A_GPMC_interface (MOD1.25)
GPMC0_AD1_MUX: PROC148A_HSECMUX (U6.23), PROC148A_PSRAM (R48.2), PROC148A_GPMC_interface (MOD1.26)
GPMC0_AD2_MUX: PROC148A_HSECMUX (U6.25), PROC148A_PSRAM (R59.2), PROC148A_GPMC_interface (MOD1.27)
GPMC0_AD3_MUX: PROC148A_HSECMUX (U6.27), PROC148A_PSRAM (R60.2), PROC148A_GPMC_interface (MOD1.28)
GPMC0_AD4_MUX: PROC148A_HSECMUX (U6.29), PROC148A_PSRAM (R61.2), PROC148A_GPMC_interface (MOD1.29)
GPMC0_AD5_MUX: PROC148A_HSECMUX (U6.32), PROC148A_PSRAM (R62.2), PROC148A_GPMC_interface (MOD1.30)
GPMC0_AD6_MUX: PROC148A_HSECMUX (U6.34), PROC148A_PSRAM (R63.2), PROC148A_GPMC_interface (MOD1.31)
GPMC0_AD7_MUX: PROC148A_HSECMUX (U6.36), PROC148A_PSRAM (R64.2), PROC148A_GPMC_interface (MOD1.32)
GPMC0_AD8_MUX: PROC148A_HSECMUX (U6.38), PROC148A_PSRAM (R65.2), PROC148A_GPMC_interface (MOD1.33)
GPMC0_AD9_MUX: PROC148A_HSECMUX (U6.39), PROC148A_PSRAM (R66.2), PROC148A_GPMC_interface (MOD1.34)
GPMC0_AD10_MUX: PROC148A_HSECMUX (U6.41), PROC148A_PSRAM (R67.2), PROC148A_GPMC_interface (MOD1.35)
GPMC0_AD11_MUX: PROC148A_HSECMUX (U5.19), PROC148A_PSRAM (R68.2), PROC148A_GPMC_interface (MOD1.36)
GPMC0_AD12_MUX: PROC148A_HSECMUX (U5.21), PROC148A_PSRAM (R69.2), PROC148A_GPMC_interface (MOD1.37)
GPMC0_AD13_MUX: PROC148A_HSECMUX (U5.23), PROC148A_PSRAM (R70.2), PROC148A_GPMC_interface (MOD1.38)
GPMC0_AD14_MUX: PROC148A_HSECMUX (U5.25), PROC148A_PSRAM (R71.2), PROC148A_GPMC_interface (MOD1.39)
GPMC0_AD15_MUX: PROC148A_HSECMUX (U5.27), PROC148A_PSRAM (R72.2), PROC148A_GPMC_interface (MOD1.40)
GPMC0_BE0N_CLE_MUX: PROC148A_HSECMUX (U7.34), PROC148A_PSRAM (R76.1 U3.A1), PROC148A_GPMC_interface (MOD1.43)
GPMC0_BE1N_MUX: PROC148A_HSECMUX (U7.36), PROC148A_PSRAM (R77.1 U3.B2), PROC148A_GPMC_interface (MOD1.44)
GPMC0_CSN0_MUX: PROC148A_HSECMUX (U4.38), PROC148A_PSRAM (R73.1 U3.B5), PROC148A_GPMC_interface (MOD1.45)
GPMC0_OEN_REN_MUX: PROC148A_HSECMUX (U7.32), PROC148A_PSRAM (R75.1 U3.A2), PROC148A_GPMC_interface (MOD1.41)
GPMC0_WAIT0_MUX: PROC148A_HSECMUX (U5.32), PROC148A_GPMC_interface (MOD1.47)
GPMC0_WEN_MUX: PROC148A_HSECMUX (U7.38), PROC148A_PSRAM (R74.1 U3.G5), PROC148A_GPMC_interface (MOD1.42)
GPMC0_WPN_MUX: PROC148A_HSECMUX (U5.29), PROC148A_GPMC_interface (MOD1.46)
HSEC_GPIO43: PROC148A_HSEC (J2.49 J20.1), PROC148A_CAN_LIN (R8.2 U1.14)
HSEC_GPIO44: PROC148A_HSEC (J2.51 J20.2), PROC148A_HSECMUX (6 pins)
HSEC_GPIO45: PROC148A_HSEC (J2.53 J20.3), PROC148A_GPMC_interface (MOD1.48)
HSEC_GPIO46: PROC148A_HSEC (J2.55 J20.4), PROC148A_GPMC_interface (MOD1.50)
HSEC_GPIO47: PROC148A_HSEC (J2.50 J21.1), PROC148A_HSECMUX (6 pins)
HSEC_GPIO48: PROC148A_HSEC (J2.52 J21.2), PROC148A_HSECMUX (U6.16)
HSEC_GPIO49: PROC148A_HSEC (J2.54 J21.3), PROC148A_CAN_LIN (R9.2 U1.11)
HSEC_GPMC0_A0: PROC148A_HSEC (J25.2 R29.2), PROC148A_HSECMUX (U5.6)
HSEC_GPMC0_A1: PROC148A_HSEC (J24.3 R30.1), PROC148A_HSECMUX (U5.5)
HSEC_GPMC0_A2: PROC148A_HSEC (J25.3 R31.2), PROC148A_HSECMUX (U5.4)
HSEC_GPMC0_A3: PROC148A_HSEC (J24.4 R32.1), PROC148A_HSECMUX (U5.3)
HSEC_GPMC0_A4: PROC148A_HSEC (J25.4 R33.2), PROC148A_HSECMUX (U5.2)
HSEC_GPMC0_A5: PROC148A_HSEC (J24.5 R34.1), PROC148A_HSECMUX (U7.16)
HSEC_GPMC0_A6: PROC148A_HSEC (J25.5 R35.2), PROC148A_HSECMUX (U7.15)
HSEC_GPMC0_A7: PROC148A_HSEC (J24.6 R40.1), PROC148A_HSECMUX (U7.14)
HSEC_GPMC0_A8: PROC148A_HSEC (J25.6 R41.2), PROC148A_HSECMUX (U7.13)
HSEC_GPMC0_A9: PROC148A_HSEC (J24.7 R42.1), PROC148A_HSECMUX (U7.12)
HSEC_GPMC0_A10: PROC148A_HSEC (J25.7 R43.2), PROC148A_HSECMUX (U7.11)
HSEC_GPMC0_A11_TRC_DATA4: PROC148A_HSEC (J24.10 R98.1), PROC148A_HSECMUX (U7.3)
HSEC_GPMC0_A12_TRC_DATA5: PROC148A_HSEC (J25.11 R99.2), PROC148A_HSECMUX (U7.2)
HSEC_GPMC0_A13_TRC_DATA6: PROC148A_HSEC (J24.11 R100.1), PROC148A_HSECMUX (U4.16)
HSEC_GPMC0_A14_TRC_DATA7: PROC148A_HSEC (J25.12 R101.2), PROC148A_HSECMUX (U4.15)
HSEC_GPMC0_A15_TRC_DATA8: PROC148A_HSEC (J24.12 R102.1), PROC148A_HSECMUX (U4.14)
HSEC_GPMC0_A16_TRC_DATA9: PROC148A_HSEC (J25.13 R103.2), PROC148A_HSECMUX (U4.13)
HSEC_GPMC0_A17_TRC_DATA10: PROC148A_HSEC (J24.13 R104.1), PROC148A_HSECMUX (U4.12)
HSEC_GPMC0_A18_TRC_DATA11: PROC148A_HSEC (J25.14 R105.2), PROC148A_HSECMUX (U4.11)
HSEC_GPMC0_A19_TRC_DATA12: PROC148A_HSEC (J24.14 R106.1), PROC148A_HSECMUX (U4.7)
HSEC_GPMC0_A20_TRC_DATA13: PROC148A_HSEC (J25.15 R107.2), PROC148A_HSECMUX (U4.6)
HSEC_GPMC0_A21_TRC_DATA14: PROC148A_HSEC (J24.15 R108.1), PROC148A_HSECMUX (U4.5)
HSEC_GPMC0_AD0: PROC148A_HSEC (J24.16 R110.1), PROC148A_HSECMUX (U6.15)
HSEC_GPMC0_AD1: PROC148A_HSEC (J25.17 R111.2), PROC148A_HSECMUX (U6.14)
HSEC_GPMC0_AD2: PROC148A_HSEC (J24.17 R112.1), PROC148A_HSECMUX (U6.13)
HSEC_GPMC0_AD3: PROC148A_HSEC (J25.18 R113.2), PROC148A_HSECMUX (U6.12)
HSEC_GPMC0_AD4: PROC148A_HSEC (J24.18 R114.1), PROC148A_HSECMUX (U6.11)
HSEC_GPMC0_AD5: PROC148A_HSEC (J25.19 R115.2), PROC148A_HSECMUX (U6.7)
HSEC_GPMC0_AD6: PROC148A_HSEC (J24.19 R116.1), PROC148A_HSECMUX (U6.6)
HSEC_GPMC0_AD7: PROC148A_HSEC (J25.20 R117.2), PROC148A_HSECMUX (U6.5)
HSEC_GPMC0_AD8: PROC148A_HSEC (J24.20 R118.1), PROC148A_HSECMUX (U6.4)
HSEC_GPMC0_AD9: PROC148A_HSEC (J25.21 R119.2), PROC148A_HSECMUX (U6.3)
HSEC_GPMC0_AD10: PROC148A_HSEC (J24.21 R120.1), PROC148A_HSECMUX (U6.2)
HSEC_GPMC0_AD11: PROC148A_HSEC (J25.22 R121.2), PROC148A_HSECMUX (U5.16)
HSEC_GPMC0_AD12: PROC148A_HSEC (J24.22 R122.1), PROC148A_HSECMUX (U5.15)
HSEC_GPMC0_AD13: PROC148A_HSEC (J25.23 R123.2), PROC148A_HSECMUX (U5.14)
HSEC_GPMC0_AD14: PROC148A_HSEC (J24.23 R124.1), PROC148A_HSECMUX (U5.13)
HSEC_GPMC0_AD15: PROC148A_HSEC (J25.24 R125.2), PROC148A_HSECMUX (U5.12)
HSEC_GPMC0_BE0N_CLE_TRC_DATA1: PROC148A_HSEC (J25.9 R45.2), PROC148A_HSECMUX (U7.6)
HSEC_GPMC0_BEN1_TRC_DATA2: PROC148A_HSEC (J24.9 R46.1), PROC148A_HSECMUX (U7.5)
HSEC_GPMC0_CLK: PROC148A_HSEC (J2.110 J21.29), PROC148A_GPMC_interface (MOD1.51)
HSEC_GPMC0_CSN0_TRC_DATA15: PROC148A_HSEC (J25.16 R109.2), PROC148A_HSECMUX (U4.4)
HSEC_GPMC0_OEN_REN_TRC_DATA0: PROC148A_HSEC (J24.8 R44.1), PROC148A_HSECMUX (U7.7)
HSEC_GPMC0_WAIT0: PROC148A_HSEC (J24.1 R27.1), PROC148A_HSECMUX (U5.7)
HSEC_GPMC0_WEN_TRC_DATA3: PROC148A_HSEC (J25.10 R97.2), PROC148A_HSECMUX (U7.4)
HSEC_GPMC0_WPN: PROC148A_HSEC (J25.1 R28.2), PROC148A_HSECMUX (U5.11)
HSEC_LIN1_RXD: PROC148A_HSEC (J2.76 J21.14), PROC148A_CAN_LIN (R88.1)
HSEC_LIN1_TXD: PROC148A_HSEC (J2.78 J21.15), PROC148A_CAN_LIN (R89.1)
HSEC_LIN3_RXD: PROC148A_HSEC (J2.73 J20.12), PROC148A_CAN_LIN (R91.1)
HSEC_LIN3_TXD: PROC148A_HSEC (J2.71 J20.11), PROC148A_CAN_LIN (R92.1)
HSEC_MCAN0_RX: PROC148A_HSEC (J2.80 J21.16), PROC148A_CAN_LIN (R4.1)
HSEC_MCAN0_TX: PROC148A_HSEC (J2.82 J21.17), PROC148A_CAN_LIN (R3.1)
HSEC_MCAN2_RX: PROC148A_HSEC (J2.94 J21.22), PROC148A_CAN_LIN (R7.1)
HSEC_MCAN2_TX: PROC148A_HSEC (J2.95 J20.22), PROC148A_CAN_LIN (R6.1)
HSEC_TCK: PROC148A_HSEC (J2.5), PROC148A_JTAG_TRACE (R82.2 U12.4)
HSEC_TDI: PROC148A_HSEC (J2.8), PROC148A_JTAG_TRACE (J10.3 R21.2 R38.2)
HSEC_TDO: PROC148A_HSEC (J2.6), PROC148A_JTAG_TRACE (J9.4 J10.7 R37.2)
HSEC_TMS: PROC148A_HSEC (J2.3), PROC148A_JTAG_TRACE (J10.1 R18.1 R39.2)
HSEC_TRC_CLK: PROC148A_HSEC (J21.10 R24.2), PROC148A_HSECMUX (U4.2)
HSEC_TRC_CTL: PROC148A_HSEC (J21.11 R26.2), PROC148A_HSECMUX (U4.3)
TRC_CLK_MUX: PROC148A_HSECMUX (U4.42), PROC148A_JTAG_TRACE (J9.13)
TRC_CTL_MUX: PROC148A_HSECMUX (U4.40), PROC148A_JTAG_TRACE (J9.17)
TRC_DATA0_MUX: PROC148A_HSECMUX (U7.31), PROC148A_JTAG_TRACE (J9.19)
TRC_DATA1_MUX: PROC148A_HSECMUX (U7.33), PROC148A_JTAG_TRACE (J9.21)
TRC_DATA2_MUX: PROC148A_HSECMUX (U7.35), PROC148A_JTAG_TRACE (J9.23)
TRC_DATA3_MUX: PROC148A_HSECMUX (U7.37), PROC148A_JTAG_TRACE (J9.25)
TRC_DATA4_MUX: PROC148A_HSECMUX (U7.40), PROC148A_JTAG_TRACE (J9.27)
TRC_DATA5_MUX: PROC148A_HSECMUX (U7.42), PROC148A_JTAG_TRACE (J9.29)
TRC_DATA6_MUX: PROC148A_HSECMUX (U4.18), PROC148A_JTAG_TRACE (J9.31)
TRC_DATA7_MUX: PROC148A_HSECMUX (U4.20), PROC148A_JTAG_TRACE (J9.33)
TRC_DATA8_MUX: PROC148A_HSECMUX (U4.22), PROC148A_JTAG_TRACE (J9.35)
TRC_DATA9_MUX: PROC148A_HSECMUX (U4.24), PROC148A_JTAG_TRACE (J9.37)
TRC_DATA10_MUX: PROC148A_HSECMUX (U4.26), PROC148A_JTAG_TRACE (J9.39)
TRC_DATA11_MUX: PROC148A_HSECMUX (U4.28), PROC148A_JTAG_TRACE (J9.41)
TRC_DATA12_MUX: PROC148A_HSECMUX (U4.31), PROC148A_JTAG_TRACE (J9.43)
TRC_DATA13_MUX: PROC148A_HSECMUX (U4.33), PROC148A_JTAG_TRACE (J9.45)
TRC_DATA14_MUX: PROC148A_HSECMUX (U4.35), PROC148A_JTAG_TRACE (J9.47)
TRC_DATA15_MUX: PROC148A_HSECMUX (U4.37), PROC148A_JTAG_TRACE (J9.49)

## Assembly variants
001: not fitted FID1 FID2 FID3 FID4 FID5 FID6 J31 J32 MOD1 R20 R22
